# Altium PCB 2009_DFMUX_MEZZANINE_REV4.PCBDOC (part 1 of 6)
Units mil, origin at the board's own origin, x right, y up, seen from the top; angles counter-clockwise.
Board outline 4922.86 x 3627.76 mil, 6 copper layers (Top Layer, Internal Plane 1, Mid-Layer 1, Internal Plane 2, Mid-Layer 2, Bottom Layer); 519 components, 606 nets, 2175 pads, 757 vias.
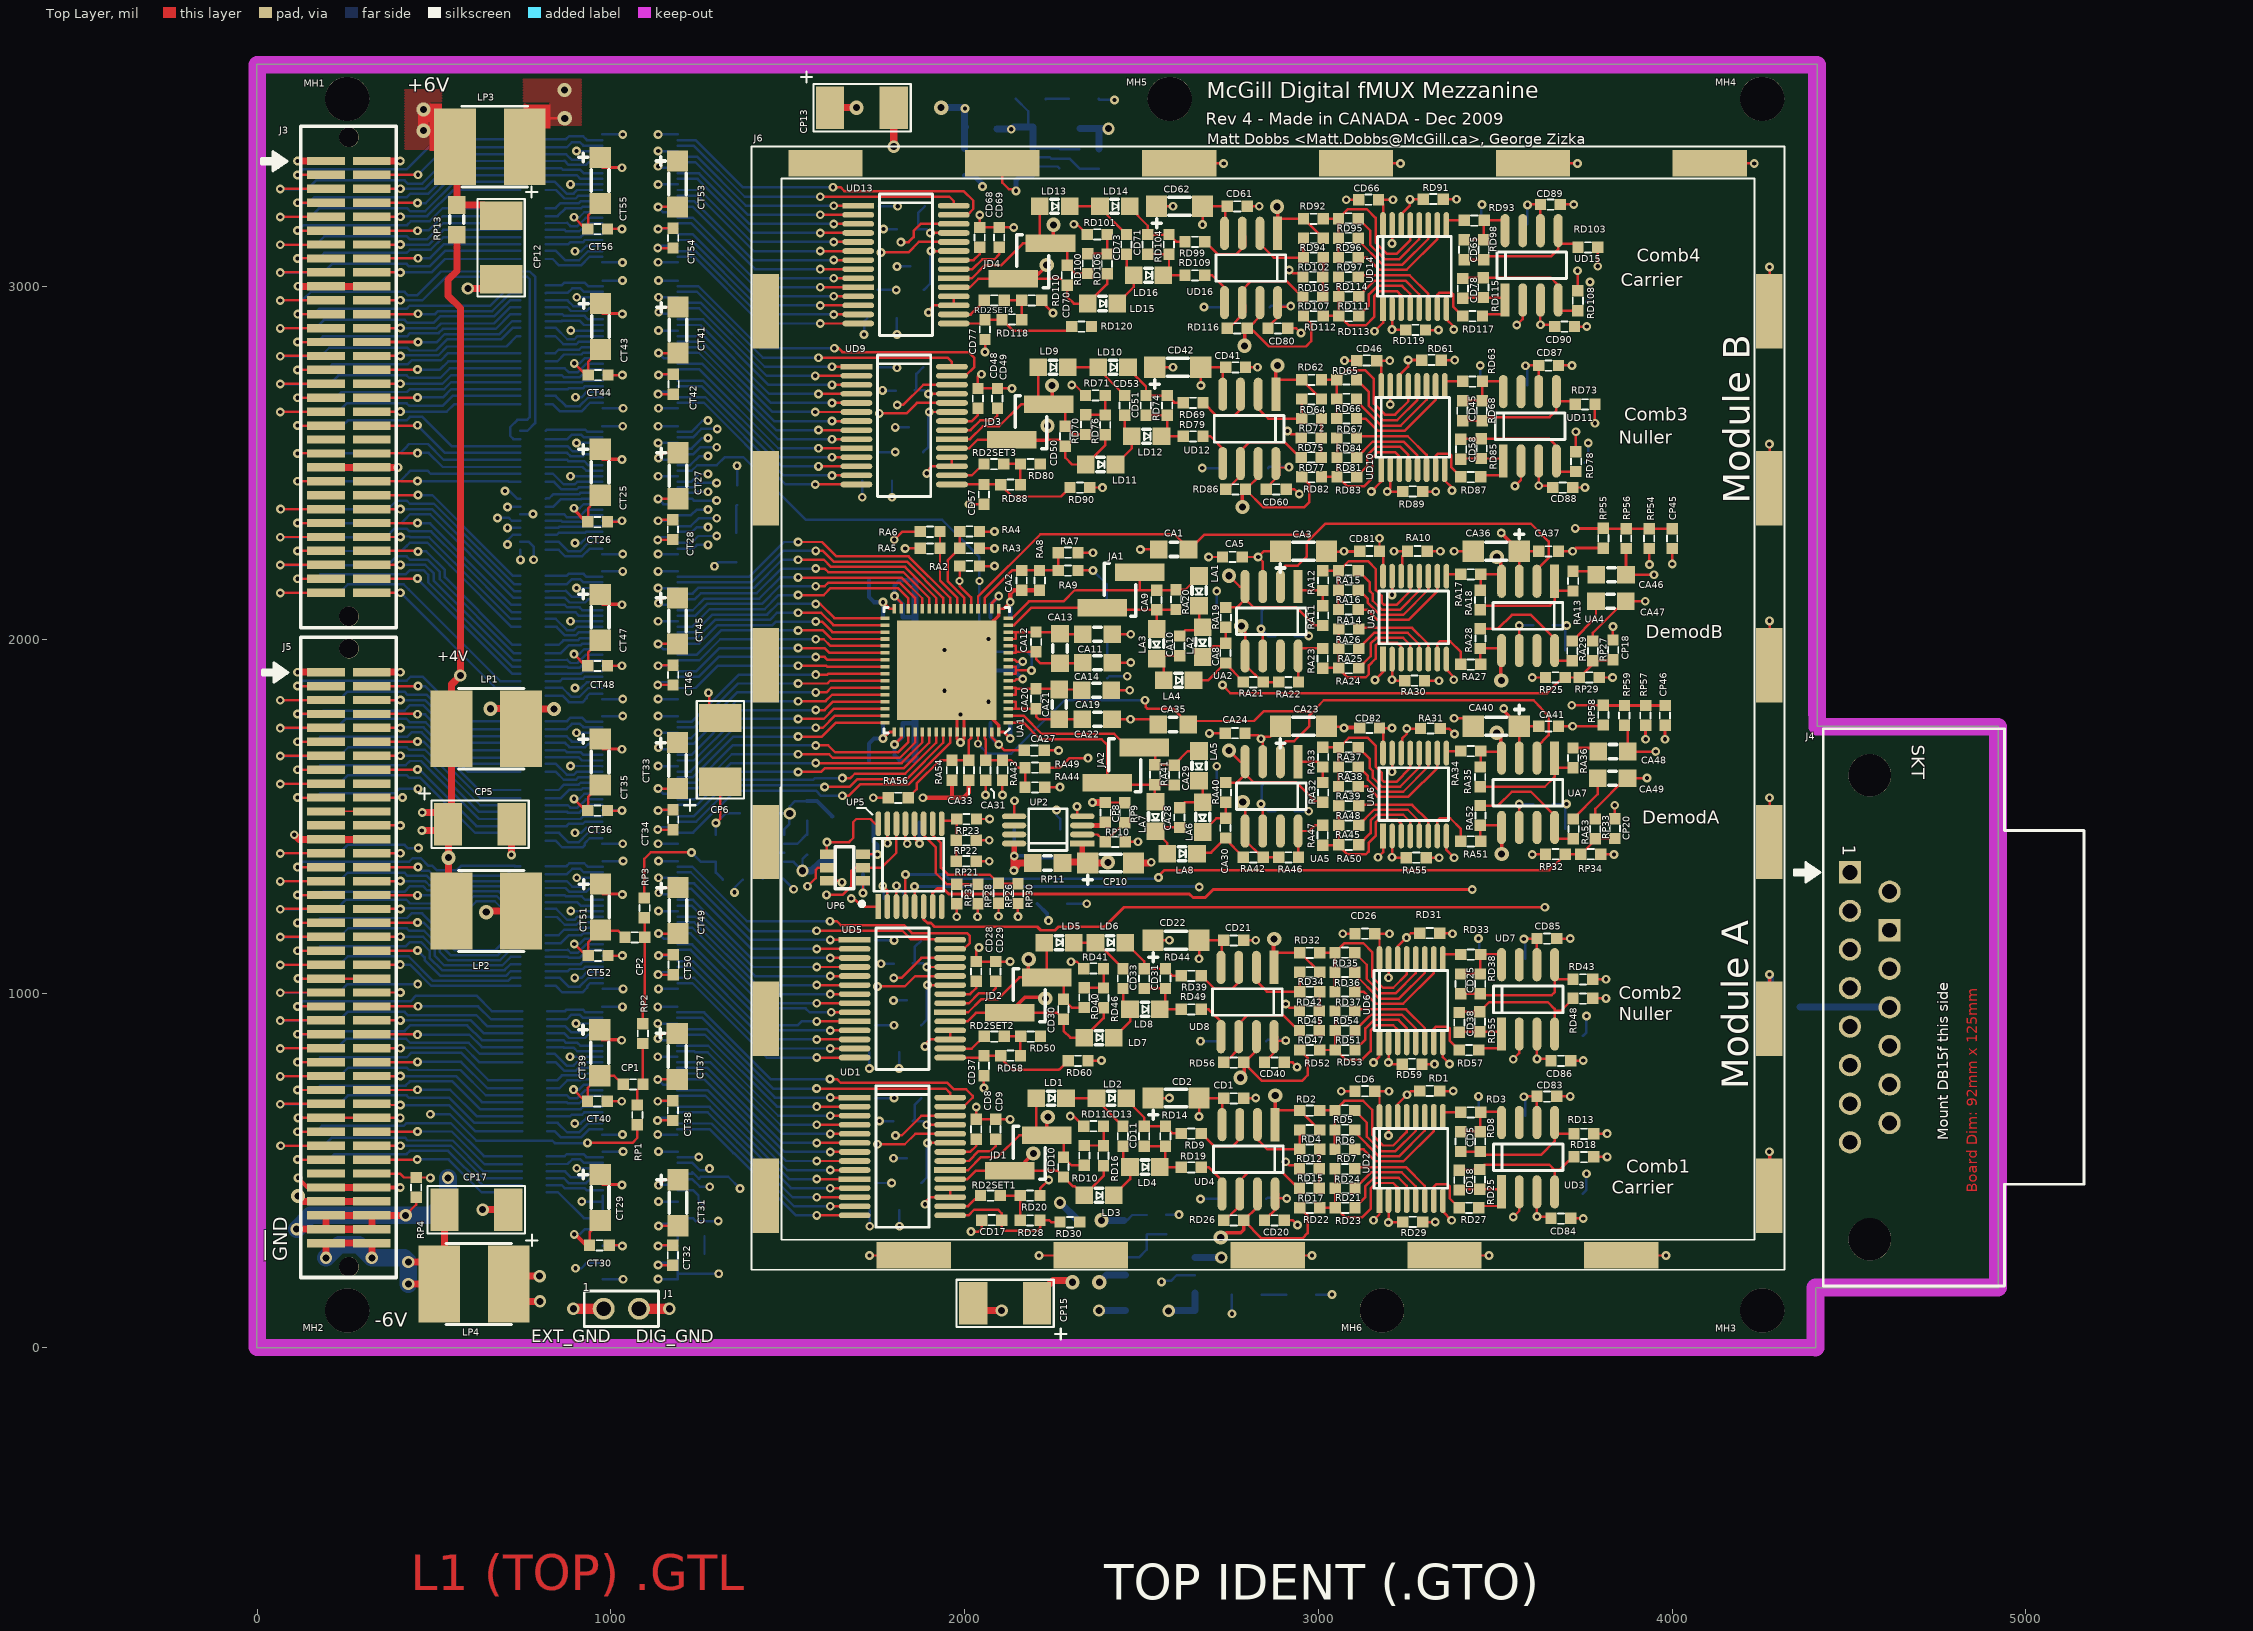
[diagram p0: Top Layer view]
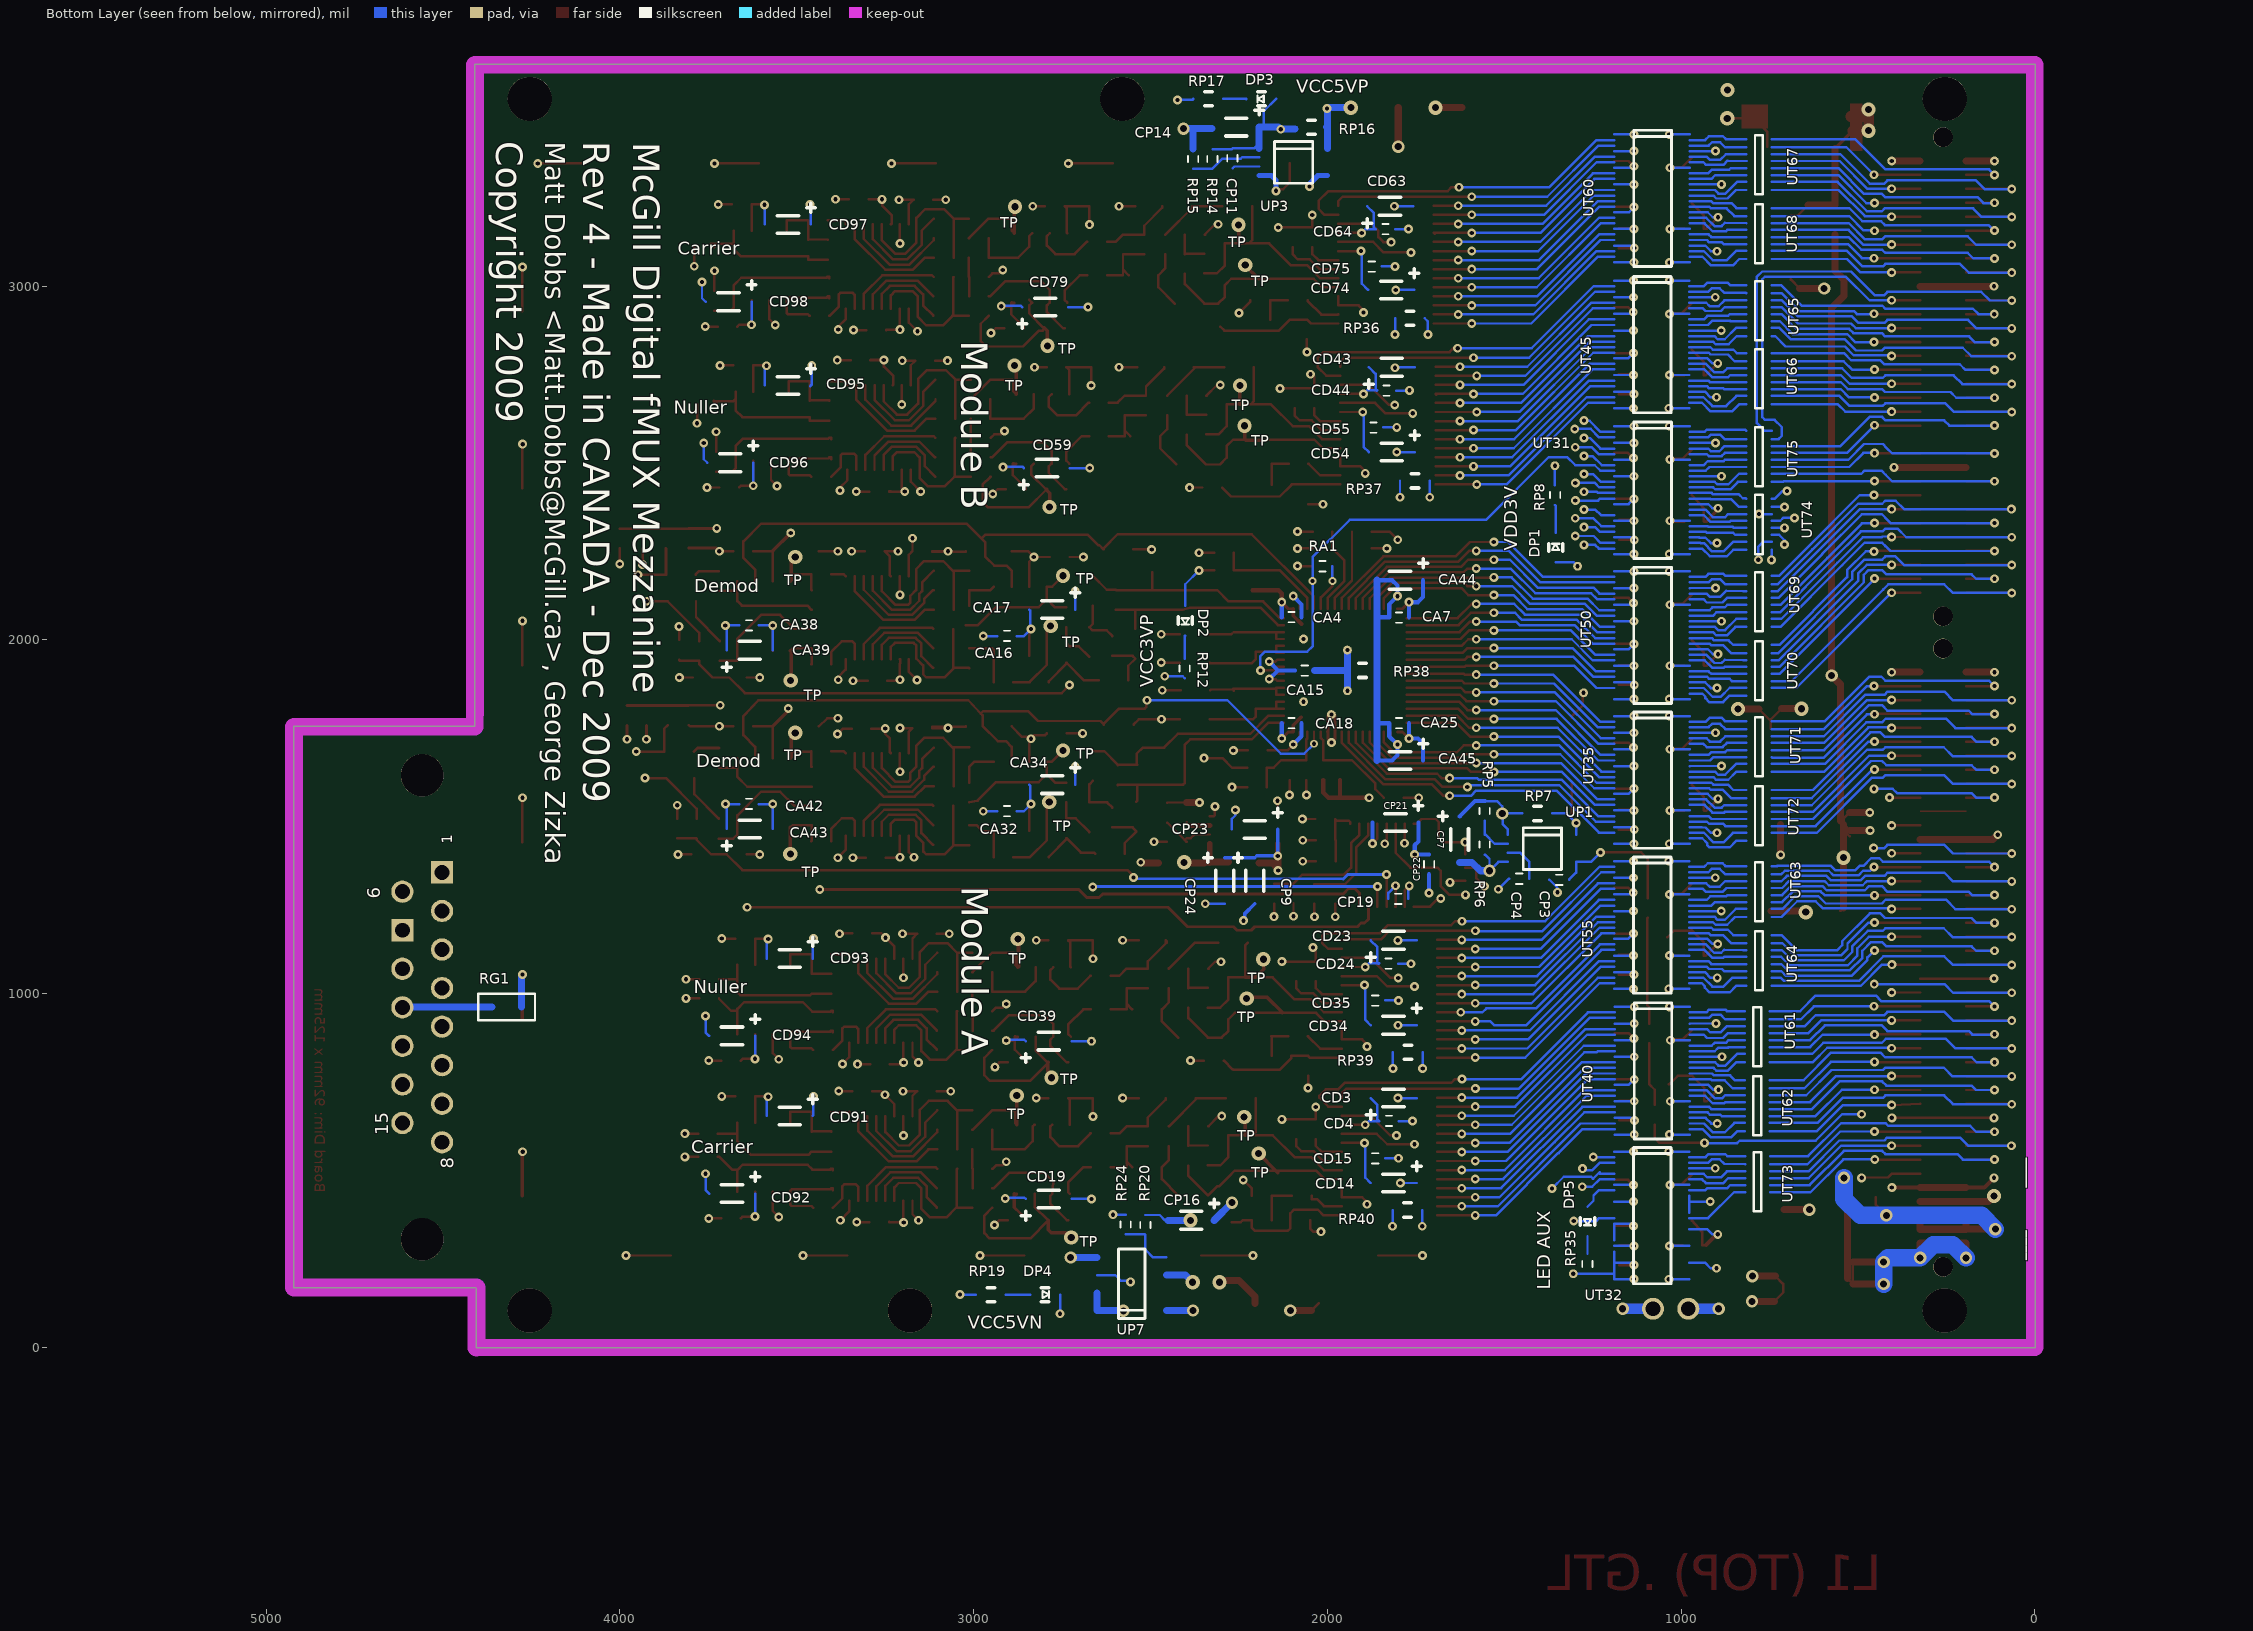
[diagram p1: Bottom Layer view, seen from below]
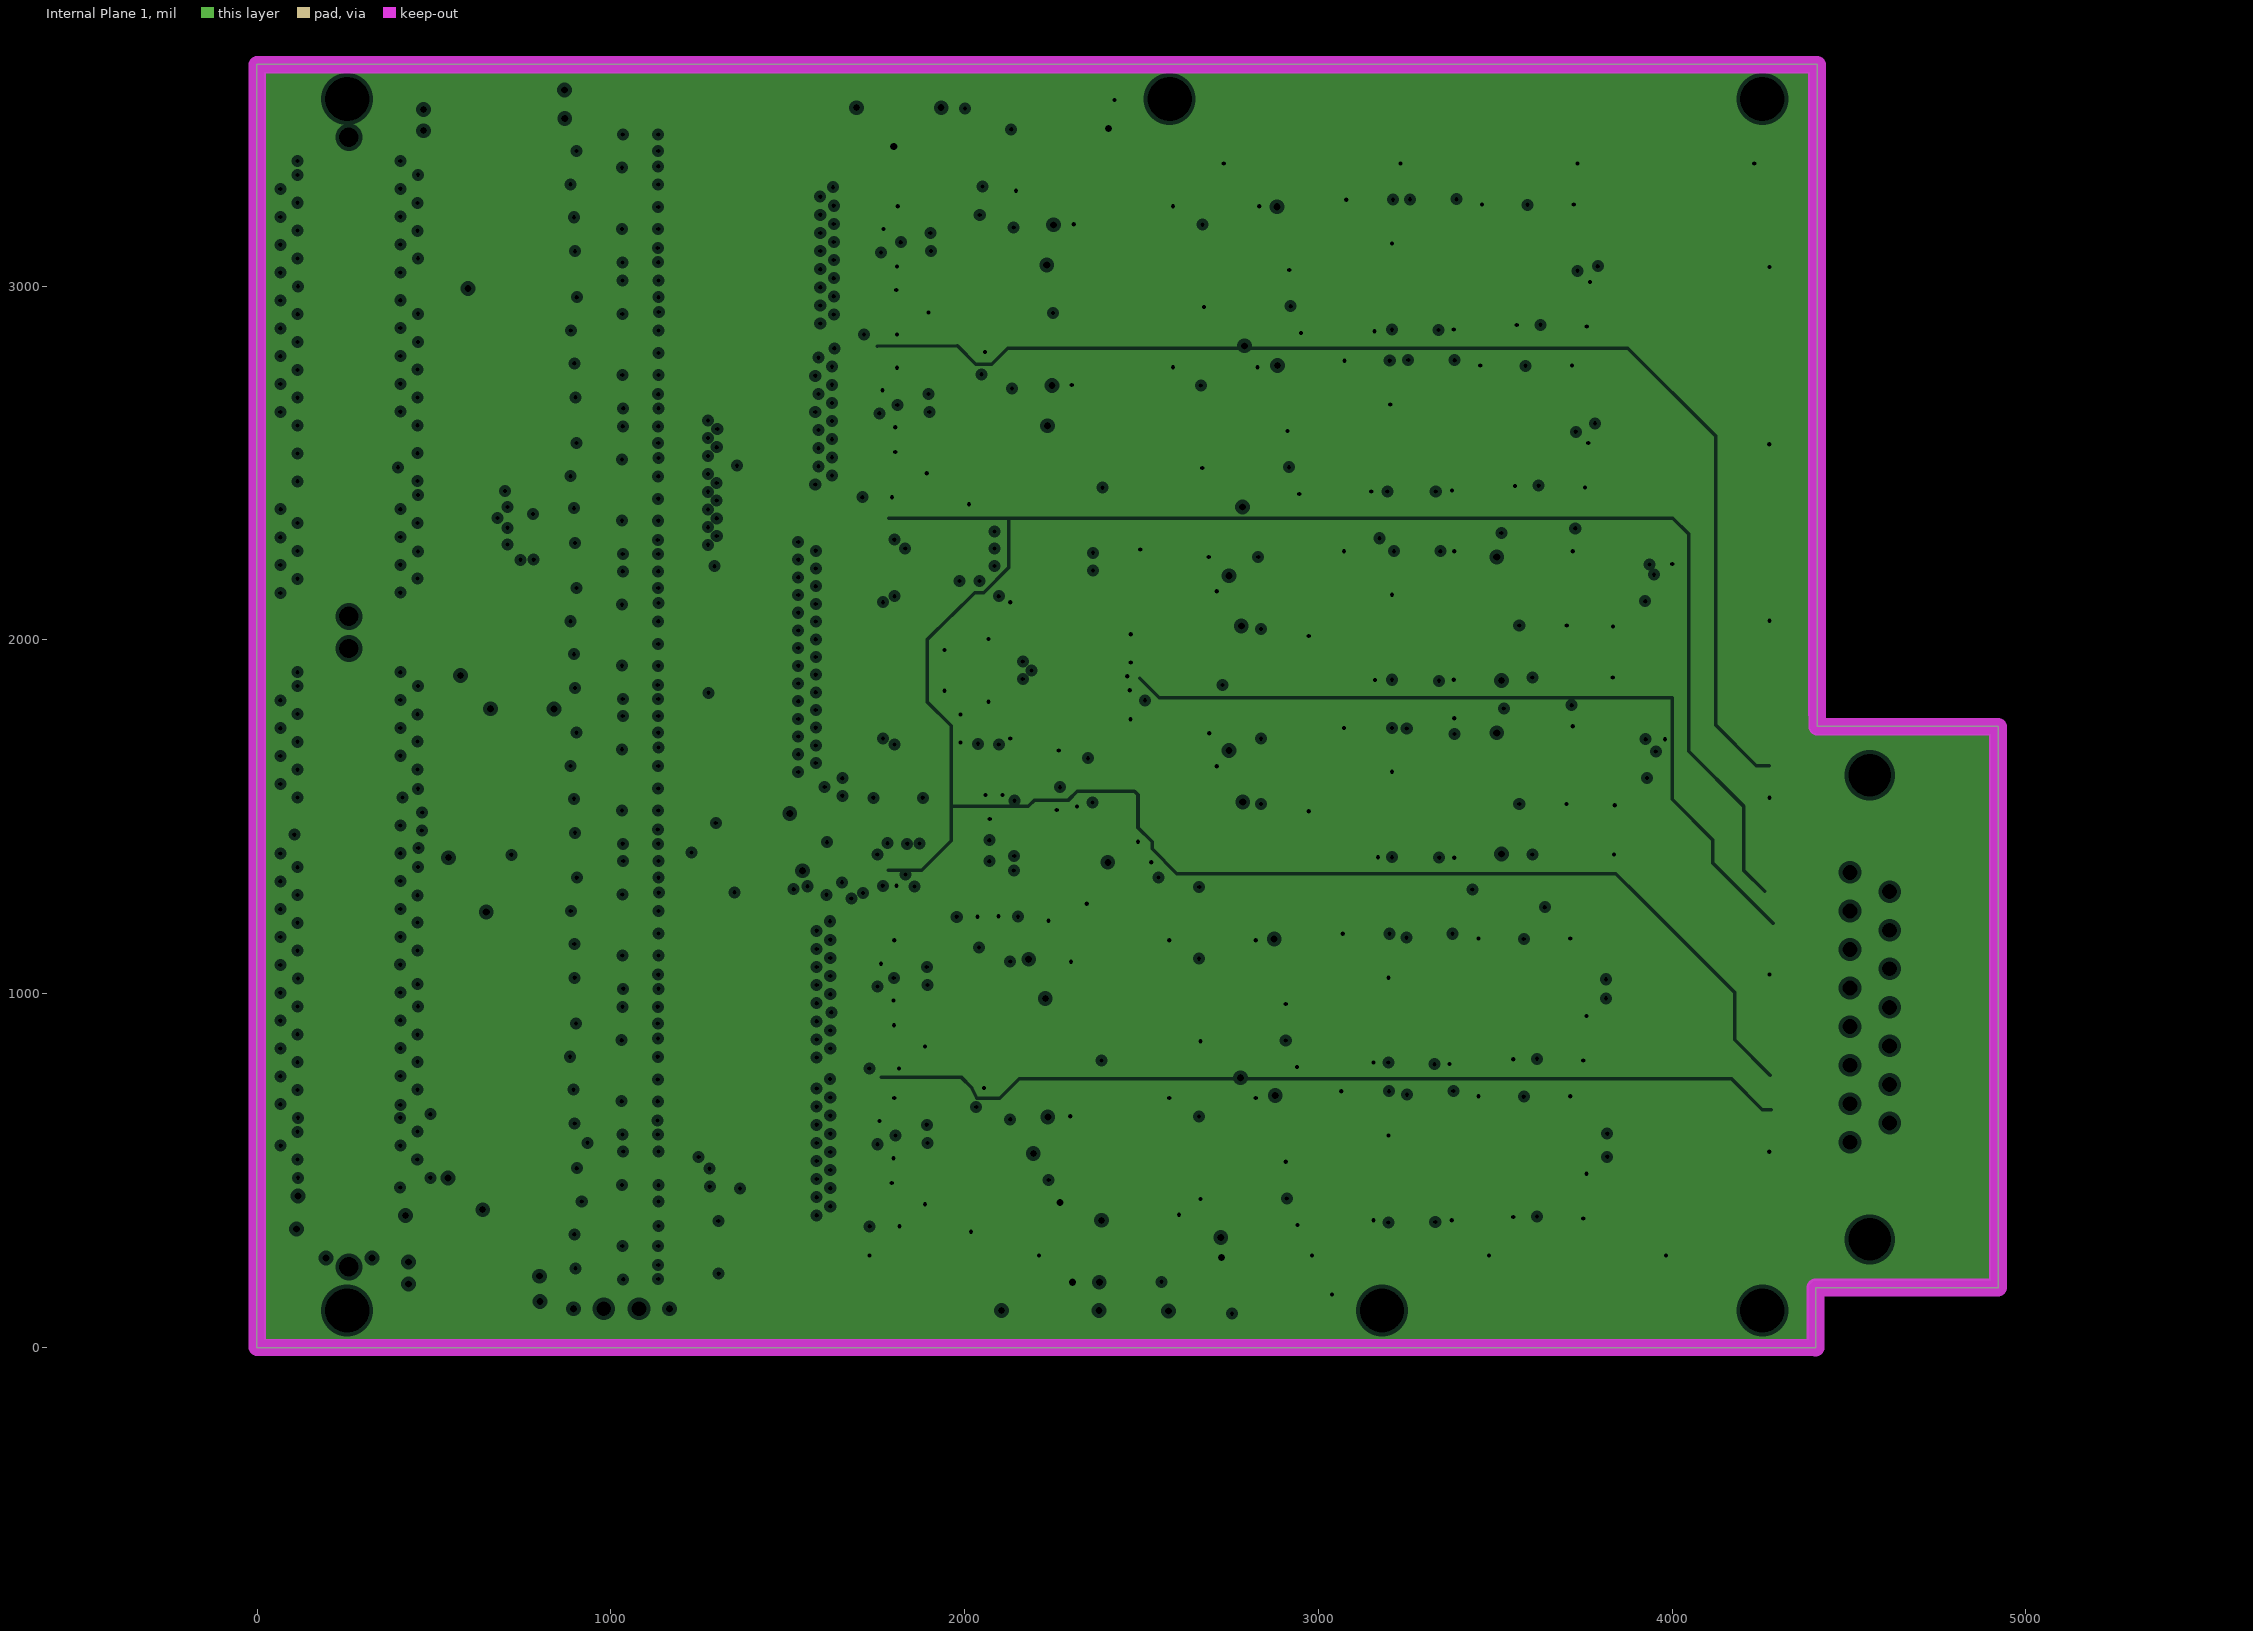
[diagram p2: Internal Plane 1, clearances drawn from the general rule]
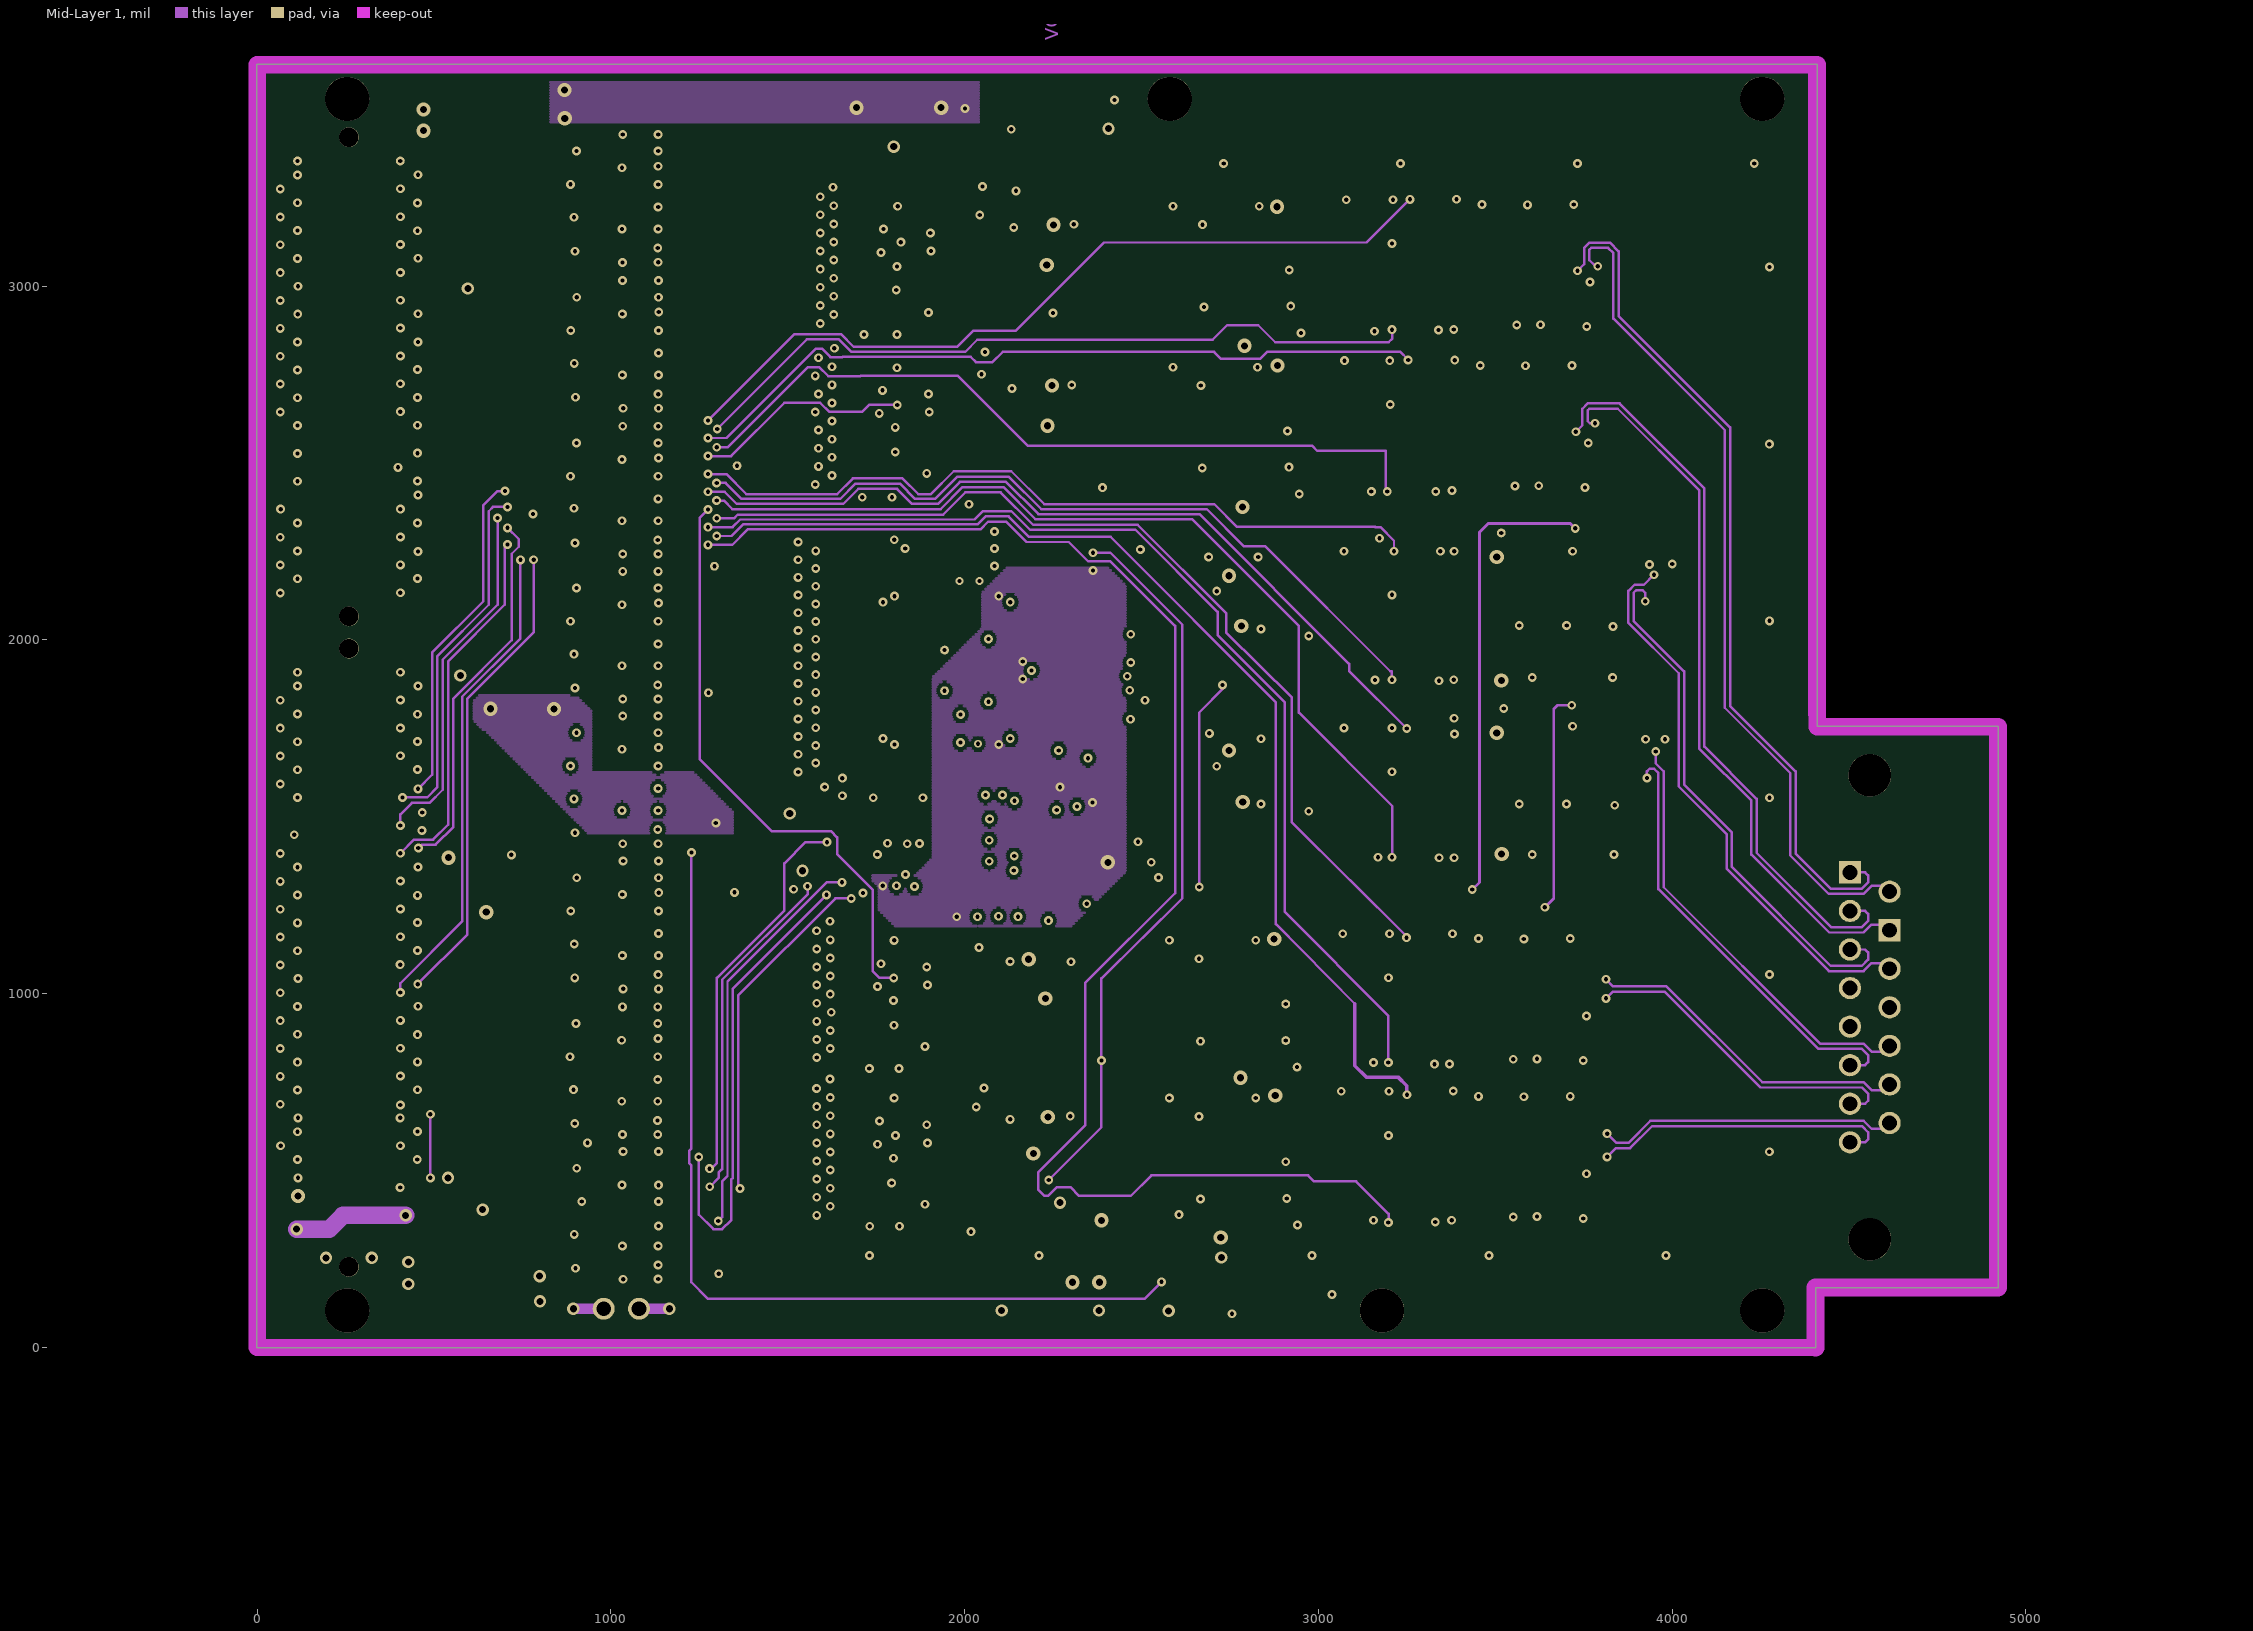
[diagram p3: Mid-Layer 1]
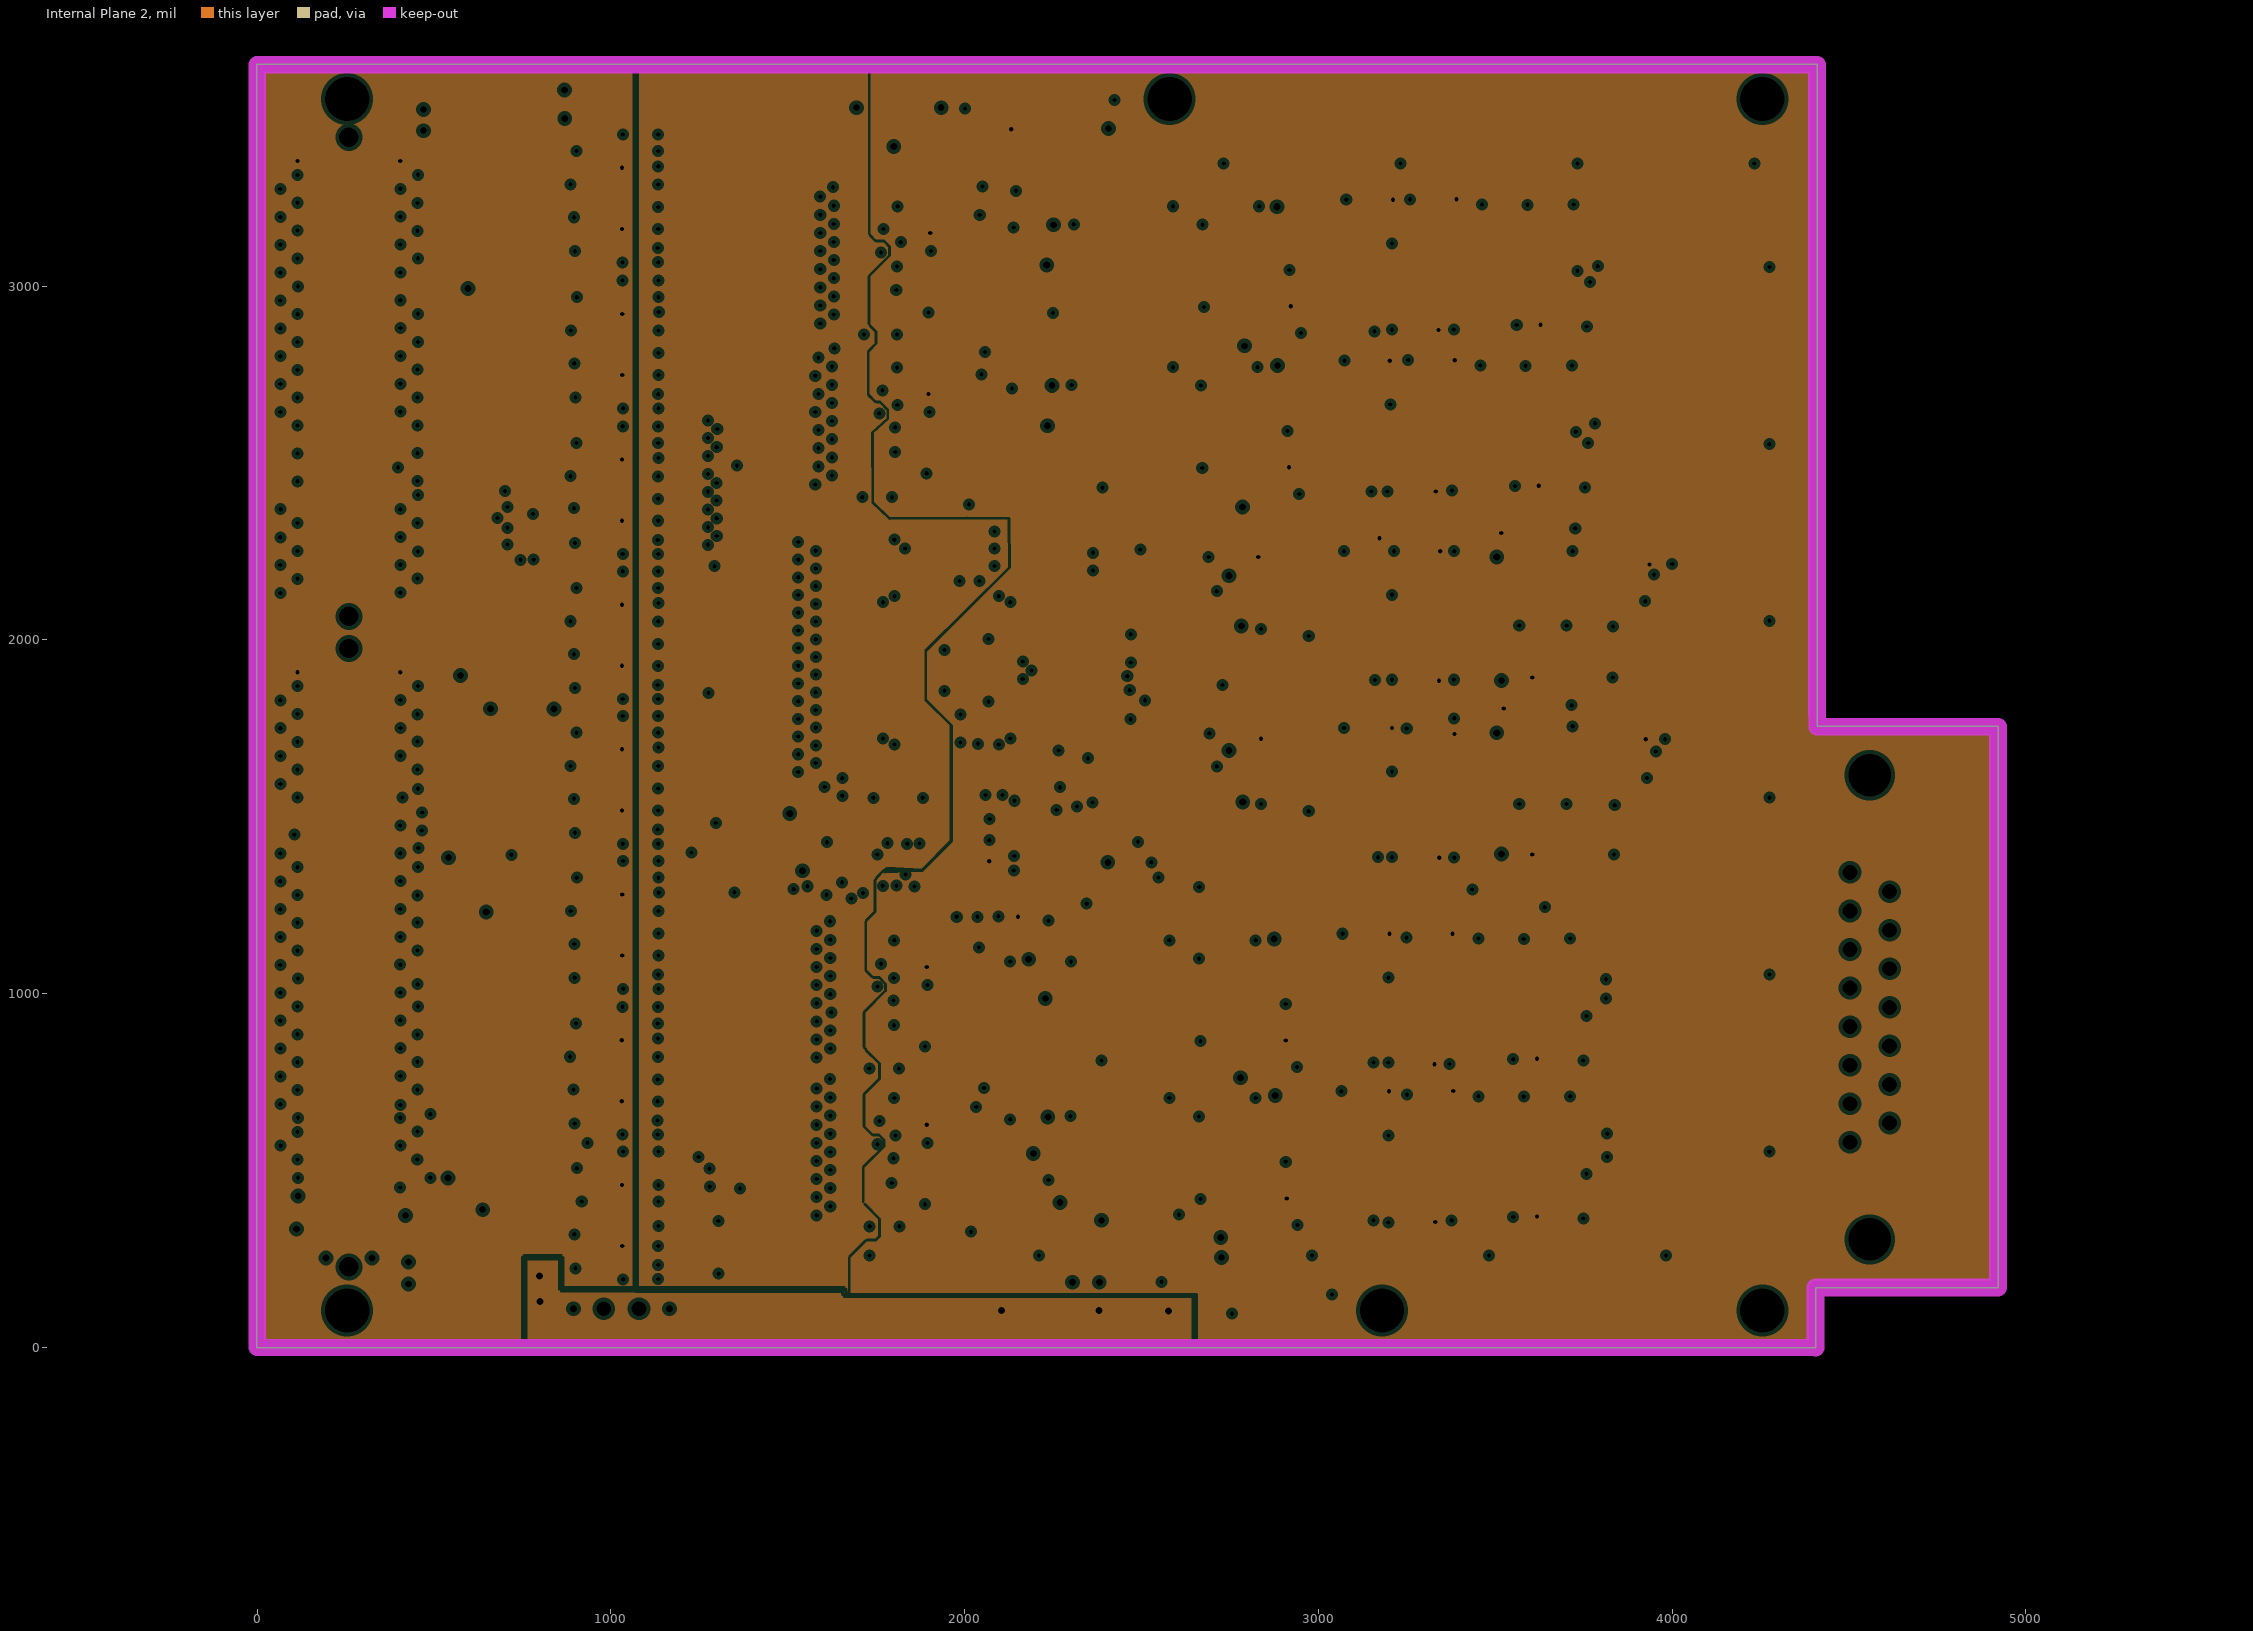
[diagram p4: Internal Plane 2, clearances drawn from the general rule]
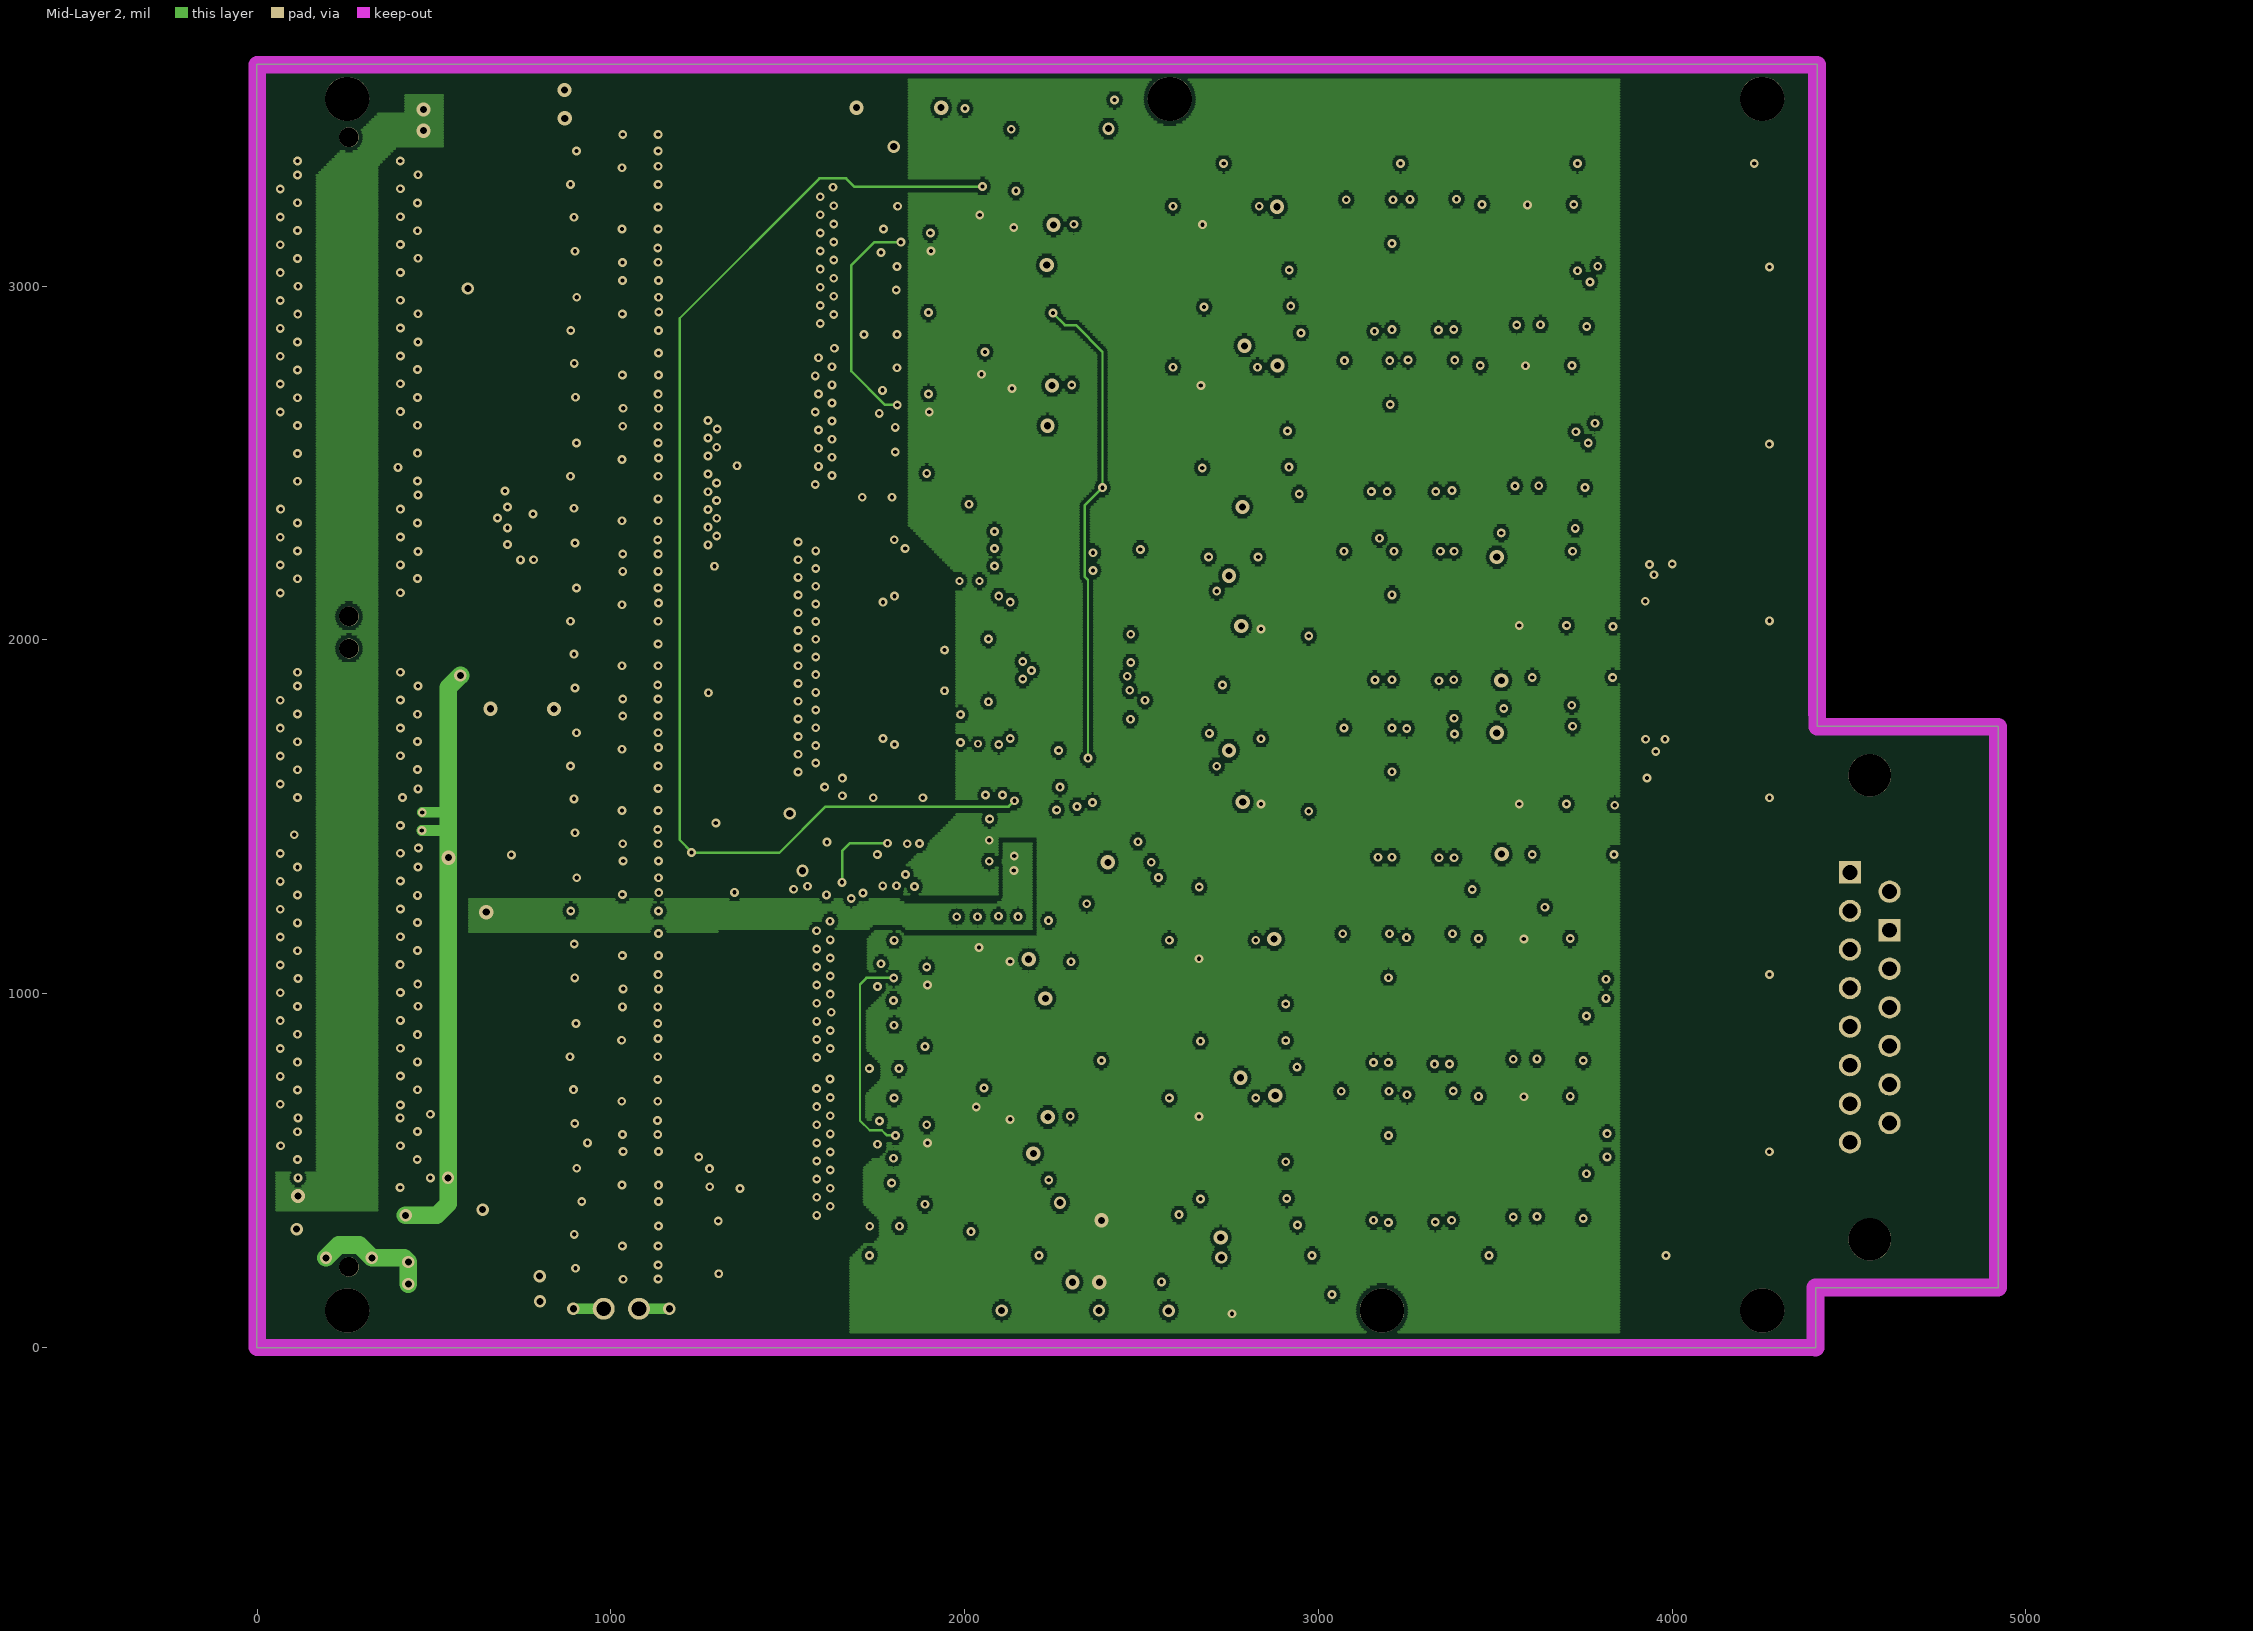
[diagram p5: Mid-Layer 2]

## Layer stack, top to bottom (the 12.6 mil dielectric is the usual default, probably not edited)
Top Layer: signal copper 1.4
Dielectric: core 12.6, FR-4, Dk 4.8
Internal Plane 1: plane copper 1.4, net GND_SIGNAL
Dielectric: prepreg 12.6, FR-4, Dk 4.8
Mid-Layer 1: signal copper 1.4
Dielectric: core 12.6, FR-4, Dk 4.8
Internal Plane 2: plane copper 1.4, net VDD_EXT
Dielectric: prepreg 12.6, FR-4, Dk 4.8
Mid-Layer 2: signal copper 1.4
Dielectric: core 12.6, FR-4, Dk 4.8
Bottom Layer: signal copper 1.4

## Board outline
0,-1.02 cw(c0,0) -1.01,0 -1.01,3625.73 cw(c0,3625.73) 0,3626.75 4409.07,3626.75 cw(c4409.07,3625.73) 4410.08,3625.73 4410.08,1755.02 4920.83,1755.02 cw(c4920.83,1754) 4921.85,1754 4921.85,169 cw(c4920.83,169) 4920.83,167.98 4406.02,167.98 4406.02,0 cw(c4405,0) 4405,-1.02

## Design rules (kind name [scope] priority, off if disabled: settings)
Clearance Clearance_1 [(InPoly)] p1: gap=10
Clearance [All] p2: gap=6
ComponentClearance [All] p1 off: gap=10 collisioncheckmode=3 verticalgap=10 showdistances=FALSE
FabricationTestPointUsage TestPointUsage [All] p1: valid=0 allowmultiple=FALSE
FabricationTestpoint Testpoint [All] p1: side=3 testpointundercomponent=TRUE minsize=40 maxsize=100 preferedsize=60 minholesize=20 maxholesize=40 preferedholesize=32 testpointgrid=1 allowsidetop=TRUE allowsidebottom=TRUE usegrid=TRUE gridtolerance=0.01
HoleSize [All] p1: absolutevalues=TRUE maxlimit=250 minlimit=10 maxpercent=80.000 minpercent=20.000
PlaneClearance [All] p1: clearance=11
PlaneConnect PlaneConnect_1 [All] p1: planeconnectstyle=Direct reliefexpansion=20 reliefentries=4 reliefconductorwidth=10 reliefairgap=10
PlaneConnect [All] p2: planeconnectstyle=Relief reliefexpansion=20 reliefentries=4 reliefconductorwidth=10 reliefairgap=12
PolygonConnect [All] p1: connectstyle=Relief reliefconductorwidth=10 reliefentries=4 polygonreliefangle="90 Angle"
RoutingLayers [All] p1: top layer_v5=TRUE mid layer 1_v5=FALSE mid layer 2_v5=FALSE bottom layer_v5=TRUE
RoutingVias [All] p1: holewidth=12 width=25 viastyle="Through Hole" minholewidth=12 minwidth=22 maxholewidth=28 maxwidth=50
SilkscreenOverComponentPads [All] p1: minsilkscreentomaskgap=10
SolderMaskExpansion [All] p1: expansion=4
Width [All] p1: maxlimit=100 minlimit=2 preferedwidth=7
20 further rules are at their usual default settings.

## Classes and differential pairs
component class "Component Group 1": CA1 CA2 CA3 CA4 CA5 CA7 CA8 CA9 CA10 CA11 CA12 CA13 CA14 CA15 CA16 CA17 CA18 CA19 CA20 CA21 CA22 CA23 CA24 CA25 CA27 CA28 CA29 CA30 CA31 CA32 CA33 CA34 CA35 CA36 CA37 CA38 CA39 CA40 CA41 CA42 CA43 CA44 CA45 CA46 CA47 CA48 CA49 CD81 CD82 JA1 JA2 LA1 LA2 LA3 LA4 LA5 LA6 LA7 LA8 RA1 RA2 RA3 RA4 RA5 RA6 RA7 RA8 RA9 RA10 RA11 RA12 RA13 RA14 RA15 RA16 RA17 RA18 RA19 RA20 RA21 RA22 RA23 RA24 RA25 RA26 RA27 RA28 RA29 RA30 RA31 RA32 RA33 RA34 RA35 RA36 RA37 RA38 RA39 RA40 RA41 RA42 RA43 RA44 RA45 RA46 RA47 RA48 RA49 RA50 RA51 RA52 RA53 RA54 RA55 RA56 UA1 UA2 UA3 UA4 UA5 UA6 UA7

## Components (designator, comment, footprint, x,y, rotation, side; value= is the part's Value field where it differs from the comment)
CA1 "2.2u, 0805, X5R" 0805C 2632.63,2255.43 r180 top
CA2 "100n, 0603" 0603C#1 2161.77,2195.87 r270 top
CA3 "10u A3216 10V LO ESR" TANTA#1 2892.63,2250.43 r0 top
CA4 "100n, 0603" 0603C#2 2073,2063.37 r0 bottom
CA5 "100n, 0603" 0603C#1 2784.63,2234 r180 top
CA7 "100n, 0603" 0603C#2 1825.27,2063.37 r180 bottom
CA8 "120p, 5%, 0603 NP0" 0603C#1 2737.63,1990.43 r270 top
CA9 "120p, 5%, 0603 NP0" 0603C#1 2542.63,2140.43 r270 top
CA10 "200p, 5%, 0603 NP0" 0603C#1 2607.63,2010.43 r270 top
CA11 "1u, 0805, X5R" 0805C 2417.63,2015.43 r180 top
CA12 "100n, 0603" 0603C#1 2201.77,1965.87 r90 top
CA13 "2.2u, 0805, X5R" 0805C 2269.63,1933.43 r90 top
CA14 "1u, 0805, X5R" 0805C 2417.63,1935.43 r180 top
CA15 "100n, 0603" 0603C#2 2091.77,1913.37 r180 bottom
CA16 "100n, 0603" 0603C#2 2877.63,2010.43 r0 bottom
CA17 "10u A3216 10V LO ESR" TANTA#2 2712.63,2085.43 r0 bottom
CA18 "100n, 0603" 0603C#2 2073,1763.91 r0 bottom
CA19 "1u, 0805, X5R" 0805C 2414.63,1857.43 r180 top
CA20 "100n, 0603" 0603C#1 2201.73,1805.37 r90 top
CA21 "2.2u, 0805, X5R" 0805C 2267.63,1775.43 r90 top
CA22 "1u, 0805, X5R" 0805C 2416.63,1775.43 r180 top
CA23 "10u A3216 10V LO ESR" TANTA#1 2892.63,1755.43 r0 top
CA24 "100n, 0603" 0603C#1 2792.63,1735.43 r180 top
CA25 "100n, 0603" 0603C#2 1769.27,1763.91 r0 bottom
CA27 "100n, 0603" 0603C#1 2168.63,1687.37 r0 top
CA28 "200p, 5%, 0603 NP0" 0603C_REV1 2607.63,1525.43 r270 top
CA29 "120p, 5%, 0603 NP0" 0603C#1 2592.63,1645.43 r270 top
CA30 "120p, 5%, 0603 NP0" 0603C#1 2737.63,1495.43 r270 top
CA31 "100n, 0603" 0603C#1 2059.27,1659.37 r270 top
CA32 "100n, 0603" 0603C#2 2877.63,1515.43 r0 bottom
CA33 "100n, 0603" 0603C#1 2011.77,1603.37 r90 top
CA34 "10u A3216 10V LO ESR" TANTA#2 2712.63,1590.43 r0 bottom
CA35 "2.2u, 0805, X5R" 0805C 2547.63,1760.43 r0 top
CA36 "10u A3216 10V LO ESR" TANTA#1 3567.63,2250.43 r180 top
CA37 "100n, 0603" 0603C#1 3622.63,2250.43 r0 top
CA38 "100n, 0603" 0603C#2 3606.63,2040.43 r0 bottom
CA39 "10u A3216 10V LO ESR" TANTA#2 3697.63,1970.43 r180 bottom
CA40 "10u A3216 10V LO ESR" TANTA#1 3567.63,1755.43 r180 top
CA41 "100n, 0603" 0603C#1 3622.63,1755.43 r0 top
CA42 "100n, 0603" 0603C#2 3606.63,1535.43 r0 bottom
CA43 "10u A3216 10V LO ESR" TANTA#2 3697.63,1465.43 r180 bottom
CA44 "10u A3216 10V LO ESR" TANTA#2 1729.27,2168.37 r0 bottom
CA45 "10u A3216 10V LO ESR" TANTA#2 1729.27,1658.91 r0 bottom
CA46 "100n, 0805" 0805C 3869.63,2184 r180 top
CA47 "100n, 0805" 0805C 3784.63,2109 r0 top
CA48 "100n, 0805" 0805C 3874.63,1684 r180 top
CA49 "100n, 0805" 0805C 3789.63,1609 r0 top
CD1 "100n, 0603" 0603C#1 2732.63,704.43 r0 top
CD2 "10u A3216 10V LO ESR" TANTA#1 2532.63,704.43 r0 top
CD3 "10u A3216 10V LO ESR" TANTA#2 1877.63,704.43 r180 bottom
CD4 "100n, 0603" 0603C#2 1797.63,639.37 r0 bottom
CD5 "DNL, 0603" 0603C#1 3402.63,609.43 r270 top
CD6 "100n, 0603" 0603C#1 3159.63,724 r180 top
CD8 "100n, 0603" 0603C#1 2032.63,644.43 r270 top
CD9 "100n, 0603" 0603C#1 2087.63,644.43 r270 top
CD10 "120p, 5%, 0603 NP0" 0603C#1 2279.63,537.43 r270 top
CD11 "120p, 5%, 0603 NP0" 0603C#1 2507.63,624.43 r270 top
CD13 "200p, 5%, 0603 NP0" 0603C#1 2447.63,624.43 r270 top
CD14 "10u A3216 10V LO ESR" TANTA#2 1747.63,464.43 r0 bottom
CD15 "100n, 0603" 0603C#2 1892.63,534.43 r180 bottom
CD17 "100n, 0603" 0603C#1 2104.63,359 r180 top
CD18 "DNL, 0603" 0603C#1 3397.63,444.43 r90 top
CD19 "10u A3216 10V LO ESR" TANTA#2 2852.63,419.43 r180 bottom
CD20 "100n, 0603" 0603C#1 2847.63,359.43 r0 top
CD21 "100n, 0603" 0603C#1 2732.63,1150.43 r0 top
CD22 "10u A3216 10V LO ESR" TANTA#1 2532.63,1150.43 r0 top
CD23 "10u A3216 10V LO ESR" TANTA#2 1877.63,1150.43 r180 bottom
CD24 "100n, 0603" 0603C#2 1799.63,1084 r0 bottom
CD25 "DNL, 0603" 0603C#1 3402.63,1055.43 r270 top
CD26 "100n, 0603" 0603C#1 3159.63,1169 r180 top
CD28 "100n, 0603" 0603C#1 2032.63,1090.43 r270 top
CD29 "100n, 0603" 0603C#1 2087.63,1090.43 r270 top
CD30 "120p, 5%, 0603 NP0" 0603C#1 2279.63,983.43 r270 top
CD31 "120p, 5%, 0603 NP0" 0603C#1 2507.63,1070.43 r270 top
CD33 "200p, 5%, 0603 NP0" 0603C#1 2447.63,1070.43 r270 top
CD34 "10u A3216 10V LO ESR" TANTA#2 1747.63,910.43 r0 bottom
CD35 "100n, 0603" 0603C#2 1892.63,980.43 r180 bottom
CD37 "100n, 0603" 0603C#1 2054.63,824 r270 top
CD38 "DNL, 0603" 0603C#1 3397.63,890.43 r90 top
CD39 "10u A3216 10V LO ESR" TANTA#2 2852.63,865.43 r180 bottom
CD40 "100n, 0603" 0603C#1 2847.63,805.43 r0 top
CD41 "100n, 0603" 0603C#1 2737.63,2770.43 r0 top
CD42 "10u A3216 10V LO ESR" TANTA#1 2537.63,2770.43 r0 top
CD43 "10u A3216 10V LO ESR" TANTA#2 1882.63,2770.43 r180 bottom
CD44 "100n, 0603" 0603C#2 1804.63,2704 r0 bottom
CD45 "DNL, 0603" 0603C#1 3407.63,2675.43 r270 top
CD46 "100n, 0603" 0603C#1 3164.63,2789 r180 top
CD48 "100n, 0603" 0603C#1 2037.63,2710.43 r270 top
CD49 "100n, 0603" 0603C#1 2092.63,2710.43 r270 top
CD50 "120p, 5%, 0603 NP0" 0603C#1 2284.63,2603.43 r270 top
CD51 "120p, 5%, 0603 NP0" 0603C#1 2512.63,2690.43 r270 top
CD53 "200p, 5%, 0603 NP0" 0603C#1 2452.63,2690.43 r270 top
CD54 "10u A3216 10V LO ESR" TANTA#2 1752.63,2530.43 r0 bottom
CD55 "100n, 0603" 0603C#2 1897.63,2600.43 r180 bottom
CD57 "100n, 0603" 0603C#1 2054.63,2439 r270 top
CD58 "DNL, 0603" 0603C#1 3402.63,2510.43 r90 top
CD59 "10u A3216 10V LO ESR" TANTA#2 2857.63,2485.43 r180 bottom
CD60 "100n, 0603" 0603C#1 2852.63,2425.43 r0 top
CD61 "100n, 0603" 0603C#1 2742.63,3225.43 r0 top
CD62 "10u A3216 10V LO ESR" TANTA#1 2542.63,3225.43 r0 top
CD63 "10u A3216 10V LO ESR" TANTA#2 1887.63,3225.43 r180 bottom
CD64 "100n, 0603" 0603C#2 1807.63,3160.37 r0 bottom
CD65 "DNL, 0603" 0603C#1 3412.63,3130.43 r270 top
CD66 "100n, 0603" 0603C#1 3169.63,3244 r180 top
CD68 "100n, 0603" 0603C#1 2042.63,3165.43 r270 top
CD69 "100n, 0603" 0603C#1 2097.63,3165.43 r270 top
CD70 "120p, 5%, 0603 NP0" 0603C#1 2289.63,3058.43 r270 top
CD71 "120p, 5%, 0603 NP0" 0603C#1 2517.63,3145.43 r270 top
CD73 "200p, 5%, 0603 NP0" 0603C#1 2457.63,3145.43 r270 top
CD74 "10u A3216 10V LO ESR" TANTA#2 1754.63,2989 r0 bottom
CD75 "100n, 0603" 0603C#2 1902.63,3055.43 r180 bottom
CD77 "100n, 0603" 0603C#1 2057.63,2905 r270 top
CD78 "DNL, 0603" 0603C#1 3407.63,2965.43 r90 top
CD79 "10u A3216 10V LO ESR" TANTA#2 2862.63,2940.43 r180 bottom
CD80 "100n, 0603" 0603C#1 2857.63,2880.43 r0 top
CD81 "100n, 0603" 0603C#1 3172.63,2250.43 r180 top
CD82 "100n, 0603" 0603C#1 3172.63,1750.43 r180 top
CD83 "100n, 0603" 0603C#1 3617.63,709.43 r0 top
CD84 "100n, 0603" 0603C#1 3657.63,364.43 r0 top
CD85 "100n, 0603" 0603C#1 3617.63,1155.43 r0 top
CD86 "100n, 0603" 0603C#1 3657.63,810.43 r0 top
CD87 "100n, 0603" 0603C#1 3622.63,2775.43 r0 top
CD88 "100n, 0603" 0603C#1 3662.63,2430.43 r0 top
CD89 "100n, 0603" 0603C#1 3627.63,3230.43 r0 top
CD90 "100n, 0603" 0603C#1 3667.63,2885.43 r0 top
CD91 "10u A3216 10V LO ESR" TANTA#2 3454.63,654 r0 bottom
CD92 "10u A3216 10V LO ESR" TANTA#2 3617.63,434.43 r0 bottom
CD93 "10u A3216 10V LO ESR" TANTA#2 3454.63,1099 r0 bottom
CD94 "10u A3216 10V LO ESR" TANTA#2 3617.63,880.43 r0 bottom
CD95 "10u A3216 10V LO ESR" TANTA#2 3459.63,2719 r0 bottom
CD96 "10u A3216 10V LO ESR" TANTA#2 3622.63,2500.43 r0 bottom
CD97 "10u A3216 10V LO ESR" TANTA#2 3459.63,3174 r0 bottom
CD98 "10u A3216 10V LO ESR" TANTA#2 3627.63,2955.43 r0 bottom
CP1 "100n 0603" 0603C#1 1034.63,744 r0 top
CP2 "100n 0603" 0603C#1 1039.63,1159 r0 top
CP3 "100n 0603" 0603C#2 1372.63,1322 r180 bottom
CP4 "10n 0603" 0603C#2 1429.63,1324 r0 bottom
CP5 "33u, 16V, 20%, 4532C, X5R" TANT4532 539.63,1478.37 r0 top
CP6 "33u, 16V, 20%, 4532C, X5R" TANT4532 1309.63,1599 r90 top
CP7 "10u A3216 10V LO ESR" TANTA#2 1625.93,1500.8 r270 bottom
CP8 "10n 0603" 0603C#1 2397.63,1484 r90 top
CP9 "33u, 16V, 20%, 4532C, X5R" TANTA#2 2205,1384 r270 bottom
CP10 "10u A3216 10V LO ESR" TANTA#1 2347.63,1369 r0 top
CP11 "10n 0603" 0603C#2 2267.63,3389 r270 bottom
CP12 "33u, 16V, 20%, 4532C, X5R" TANT4532 689.63,3199 r270 top
CP13 "33u, 16V, 20%, 4532C, X5R" TANT4532 1619.63,3504 r0 top
CP14 "10u A3216 10V LO ESR" TANTA#2 2192.63,3449 r0 bottom
CP15 "33u, 16V, 20%, 4532C, X5R" TANT4532 2204.63,124 r180 top
CP16 "10u A3216 10V LO ESR" TANTA#2 2319.63,359 r0 bottom
CP17 "33u, 16V, 20%, 4532C, X5R" TANT4532 709.63,389 r180 top
CP18 "100n, 0603" 0603C#1 3832.63,1943.37 r90 top
CP19 "100n, 0603" 0603C#2 1827.63,1268.37 r180 bottom
CP20 "100n, 0603" 0603C#1 3837.63,1438.37 r90 top
CP21 "10u A3216 10V LO ESR" TANTA#2 1742.63,1483.37 r0 bottom
CP22 "100n, 0603" 0603C#2 1712.63,1337.37 r90 bottom
CP23 "10uF,3216,low ESR" TANTA#2 2140,1464 r0 bottom
CP24 "10uF,3216,low ESR" TANTA#2 2290,1384 r270 bottom
CP45 "100n, 0603" 0603C#1 4000,2314 r270 top
CP46 "100n, 0603" 0603C#1 3980,1814 r270 top
CT25 "10u A3216 10V LO ESR" TANTA#1 969.63,2538.37 r270 top
CT26 "100n, 0603" 0603C#1 934.63,2333.37 r0 top
CT27 "10u A3216 10V LO ESR" TANTA#1 1189.63,2528.37 r270 top
CT28 "100n, 0603" 0603C#1 1174.63,2283.37 r90 top
CT29 "10u A3216 10V LO ESR" TANTA#1 969.63,488.37 r270 top
CT30 "100n, 0603" 0603C#1 939.63,288.37 r0 top
CT31 "10u A3216 10V LO ESR" TANTA#1 1189.63,473.37 r270 top
CT32 "100n, 0603" 0603C#1 1174.63,232.37 r90 top
CT33 "10u A3216 10V LO ESR" TANTA#1 1188.63,1709.37 r270 top
CT34 "100n, 0603" 0603C#1 1175.63,1463.37 r90 top
CT35 "10u A3216 10V LO ESR" TANTA#1 969.63,1719.37 r270 top
CT36 "100n, 0603" 0603C#1 934.63,1517.37 r0 top
CT37 "10u A3216 10V LO ESR" TANTA#1 1187.63,887.37 r270 top
CT38 "100n, 0603" 0603C#1 1174.63,641.37 r90 top
CT39 "10u A3216 10V LO ESR" TANTA#1 968.63,897.37 r270 top
CT40 "100n, 0603" 0603C#1 933.63,695.37 r0 top
CT41 "10u A3216 10V LO ESR" TANTA#1 1189.63,2940.37 r270 top
CT42 "100n, 0603" 0603C#1 1176.63,2694.37 r90 top
CT43 "10u A3216 10V LO ESR" TANTA#1 970.63,2950.37 r270 top
CT44 "100n, 0603" 0603C#1 935.63,2748.37 r0 top
CT45 "10u A3216 10V LO ESR" TANTA#1 1188.63,2118.37 r270 top
CT46 "100n, 0603" 0603C#1 1175.63,1872.37 r90 top
CT47 "10u A3216 10V LO ESR" TANTA#1 969.63,2128.37 r270 top
CT48 "100n, 0603" 0603C#1 934.63,1926.37 r0 top
CT49 "10u A3216 10V LO ESR" TANTA#1 1189.63,1299.37 r270 top
CT50 "100n, 0603" 0603C#1 1176.63,1053.37 r90 top
CT51 "10u A3216 10V LO ESR" TANTA#1 970.63,1309.37 r270 top
CT52 "100n, 0603" 0603C#1 935.63,1107.37 r0 top
CT53 "10u A3216 10V LO ESR" TANTA#1 1188.63,3353.37 r270 top
CT54 "100n, 0603" 0603C#1 1175.63,3107.37 r90 top
CT55 "10u A3216 10V LO ESR" TANTA#1 969.63,3363.37 r270 top
CT56 "100n, 0603" 0603C#1 934.63,3161.37 r0 top
DP1 "LED, 0805, Green" 0805L#1 1354.63,2219 r90 bottom
DP2 "LED, 0805, Green" 0805L#1 2401.63,2096 r270 bottom
DP3 "LED, 0805, Green" 0805L#1 2144.63,3529 r0 bottom
DP4 "LED, 0805, Green" 0805L#1 2839.63,149 r180 bottom
DP5 "LED, 0805, Yellow" 0805L#1 1264.63,397.37 r270 bottom
J1 "Header SM Amp146128-1" BLKCON.100/VH/TM1SQS/W.100/2 979.63,109 r0 top
J3 "IEEE1386 Amp120527-1 Plug 64pin" CON_AMP_1MM_64PINS 194.63,3353.43 r90 top
J4 "DB15_FEMALE" DSUB/RS.318/TM/15 4502.5,1342.5 r270 top locked
J5 "IEEE1386 Amp120527-2 Plug 84pin" CON_AMP_1MM_84PINS 194.63,1908.37 r90 top
J6 "CONN FLEX 23" "SHIELD 2.75X3.00" 4237.63,3309 r270 top locked
JA1 "Header2, SM, 0.1" HEADER_AMP146128 2494.27,2190.87 r270 top
JA2 "Header2, SM, 0.1" HEADER_AMP146128 2507.63,1695.43 r270 top
JD1 "Header2, SM, 0.1" HEADER_AMP146128 2127.63,499.43 r90 top
JD2 "Header2, SM, 0.1" HEADER_AMP146128 2127.63,945.43 r90 top
JD3 "Header2, SM, 0.1" HEADER_AMP146128 2132.63,2565.43 r90 top
JD4 "Header2, SM, 0.1" HEADER_AMP146128 2137.63,3020.43 r90 top
LA1 "2.7uH, 0805" 0805L#2 2662.63,2180.43 r270 top
LA2 "2.7uH, 0805" 0805L#2 2672.63,2035.43 r270 top
LA3 "2.7uH, 0805" 0805L#2 2542.63,2030.43 r270 top
LA4 "2.7uH, 0805" 0805L#2 2562.63,1885.43 r0 top
LA5 "2.7uH, 0805" 0805L#2 2662.63,1685.43 r270 top
LA6 "2.7uH, 0805" 0805L#2 2672.63,1540.43 r270 top
LA7 "2.7uH, 0805" 0805L#2 2539.63,1542.43 r270 top
LA8 "2.7uH, 0805" 0805L#2 2572.63,1395.43 r0 top
LD1 "2.7uH, 0805" 0805L#2 2202.63,704.43 r0 top
LD2 "2.7uH, 0805" 0805L#2 2372.63,704.43 r0 top
LD3 "2.7uH, 0805" 0805L#2 2337.63,429.43 r0 top
LD4 "2.7uH, 0805" 0805L#2 2467.63,509.43 r0 top
LD5 "2.7uH, 0805" 0805L#2 2224.63,1144 r0 top
LD6 "2.7uH, 0805" 0805L#2 2369.63,1144 r0 top
LD7 "2.7uH, 0805" 0805L#2 2337.63,875.43 r0 top
LD8 "2.7uH, 0805" 0805L#2 2467.63,955.43 r0 top
LD9 "2.7uH, 0805" 0805L#2 2207.63,2770.43 r0 top
LD10 "2.7uH, 0805" 0805L#2 2377.63,2770.43 r0 top
LD11 "2.7uH, 0805" 0805L#2 2342.63,2495.43 r0 top
LD12 "2.7uH, 0805" 0805L#2 2472.63,2575.43 r0 top
LD13 "2.7uH, 0805" 0805L#2 2212.63,3225.43 r0 top
LD14 "2.7uH, 0805" 0805L#2 2382.63,3225.43 r0 top
LD15 "2.7uH, 0805" 0805L#2 2347.63,2950.43 r0 top
LD16 "2.7uH, 0805" 0805L#2 2477.63,3030.43 r0 top
LP1 "68uH, 0.61A, 460mOhm, PM54-680K" CHOKEPM54 549.63,1748.37 r0 top
LP2 "68uH, 0.61A, 460mOhm, PM54-680K" CHOKEPM54 549.63,1233.37 r0 top
LP3 "68uH, 0.61A, 460mOhm, PM54-680K" CHOKEPM54 559.63,3394 r0 top
LP4 "68uH, 0.61A, 460mOhm, PM54-680K" CHOKEPM54 514.63,179 r0 top
MH1 "mounting hole" MTHOLE.125 254.63,3529 r0 top
MH2 "mounting hole" MTHOLE.125 254.63,104 r0 top
MH3 "mounting hole" MTHOLE.125 4254.63,104 r0 top
MH4 "mounting hole" MTHOLE.125 4254.63,3529 r0 top
MH5 "mounting hole" MTHOLE.125 2579.63,3529 r0 top
MH6 "mounting hole" MTHOLE.125 3179.63,104 r0 top
RA1 "DNL, 0603" 0603R#1 2041.77,2208.37 r180 bottom
RA2 "0, 0603" 0603R#2 2041.77,2208.37 r180 top
RA3 "0, 0603" 0603R#2 2041.77,2258.37 r180 top
RA4 "DNL, 0603" 0603R#2 2041.77,2305.87 r180 top
RA5 "0, 0603" 0603R#2 1874.27,2258.37 r0 top
RA6 "DNL, 0603" 0603R#2 1874.27,2305.87 r0 top
RA7 "DNL, 0603" 0603R#2 2320.27,2245.87 r180 top
RA8 "DNL, 0603" 0603R#2 2211.77,2139.87 r90 top
RA9 "0, 0603" 0603R#2 2264.27,2195.87 r0 top
RA10 "10K, 1%, 0603" 0603R#2 3307.63,2250.43 r180 top
RA11 "806, 1%, 0603" 0603R#2 3012.63,2040.43 r90 top
RA12 "49.9, 1%, 0603" 0603R#2 3012.63,2139.43 r90 top
RA13 "49.9, 1%, 0603" 0603R#2 3719.63,2138 r90 top
RA14 "698, 1%, 0603" 0603R#2 3112.63,2085.43 r180 top
RA15 "100, 1%, 0603" 0603R#2 3112.63,2195.43 r180 top
RA16 "301, 1%, 0603" 0603R#2 3112.63,2140.43 r180 top
RA17 "49.9, 1%, 0603" 0603R#2 3402.63,2185.43 r0 top
RA18 "100, 1%, 0603" 0603R#2 3457.63,2140.43 r270 top
RA19 "49.9, 1%, 0603" 0603R#2 2737.63,2035.43 r90 top
RA20 "100, 1%, 0603" 0603R#2 2597.63,2085.43 r90 top
RA21 "49.9, 1%, 0603" 0603R#2 2787.63,1880.43 r0 top
RA22 "806, 1%, 0603" 0603R#2 2887.63,1880.43 r0 top
RA23 "49.9, 1%, 0603" 0603R#2 3012.63,1975.43 r270 top
RA24 "100, 1%, 0603" 0603R#2 3057.63,1920.43 r0 top
RA25 "301, 1%, 0603" 0603R#2 3057.63,1975.43 r0 top
RA26 "698, 1%, 0603" 0603R#2 3057.63,2030.43 r0 top
RA27 "49.9, 1%, 0603" 0603R#2 3402.63,1930.43 r0 top
RA28 "100, 1%, 0603" 0603R#2 3457.63,1975.43 r90 top
RA29 "49.9, 1%, 0603" 0603R#2 3717.63,1940.43 r90 top
RA30 "10K, 1%, 0603" 0603R#2 3299.63,1884 r180 top
RA31 "10K, 1%, 0603" 0603R#2 3344.63,1749 r180 top
RA32 "806, 1%, 0603" 0603R#2 3012.63,1540.43 r90 top
RA33 "49.9, 1%, 0603" 0603R#2 3012.63,1640.43 r90 top
RA34 "49.9, 1%, 0603" 0603R#2 3402.63,1685.43 r0 top
RA35 "100, 1%, 0603" 0603R#2 3457.63,1640.43 r270 top
RA36 "49.9, 1%, 0603" 0603R#2 3719.63,1638 r90 top
RA37 "100, 1%, 0603" 0603R#2 3112.63,1695.43 r180 top
RA38 "301, 1%, 0603" 0603R#2 3112.63,1640.43 r180 top
RA39 "698, 1%, 0603" 0603R#2 3112.63,1585.43 r180 top
RA40 "49.9, 1%, 0603" 0603R#2 2737.63,1540.43 r90 top
RA41 "100, 1%, 0603" 0603R#2 2537.63,1590.43 r90 top
RA42 "49.9, 1%, 0603" 0603R#2 2787.63,1385.43 r0 top
RA43 "DNL, 0603" 0603R#2 2106.77,1603.37 r90 top
RA44 "0, 0603" 0603R#2 2170.77,1583.37 r0 top
RA45 "301, 1%, 0603" 0603R#2 3057.63,1475.43 r0 top
RA46 "806, 1%, 0603" 0603R#2 2887.63,1385.43 r0 top
RA47 "49.9, 1%, 0603" 0603R#2 3012.63,1475.43 r270 top
RA48 "698, 1%, 0603" 0603R#2 3057.63,1530.43 r0 top
RA49 "DNL, 0603" 0603R#2 2226.77,1638.37 r180 top
RA50 "100, 1%, 0603" 0603R#2 3057.63,1420.43 r0 top
RA51 "49.9, 1%, 0603" 0603R#2 3402.63,1430.43 r0 top
RA52 "100, 1%, 0603" 0603R#2 3457.63,1475.43 r90 top
RA53 "49.9, 1%, 0603" 0603R#2 3720.63,1437.43 r90 top
RA54 "DNL, 0603" 0603R#2 1964.27,1659.37 r270 top
RA55 "10K, 1%, 0603" 0603R#2 3304.63,1384 r180 top
RA56 "0, 0603" 0603R#2 1784.27,1553.37 r0 top
RD1 "10K, 1%, 0603" 0603R#2 3342.63,724.43 r180 top
RD2 "49.9, 1%, 0603" 0603R#2 2947.63,669.43 r0 top
RD2SET1 "2K, 1%, 0603" 0603R#2 2044.63,429 r0 top
RD2SET2 "2K, 1%, 0603" 0603R#2 2055.63,879 r0 top
RD2SET3 "2K, 1%, 0603" 0603R#2 2054.63,2497 r0 top
RD2SET4 "2K, 1%, 0603" 0603R#2 2055.63,2960 r0 top
RD3 "49.9, 1%, 0603" 0603R#2 3402.63,664.43 r0 top
RD4 "200, 0603, 1%" 0603R#2 2947.63,614.43 r0 top
RD5 "100, 1%, 0603" 0603R#2 3102.63,669.43 r180 top
RD6 "301, 1%, 0603" 0603R#2 3102.63,614.43 r180 top
RD7 "698, 1%, 0603" 0603R#2 3102.63,559.43 r180 top
RD8 "806, 1%, 0603" 0603R#2 3457.63,609.43 r270 top
RD9 "0, 1%, 0603" 0603R#2 2612.63,604.43 r0 top
RD10 "49.9, 1%, 0603" 0603R#2 2337.63,514.43 r90 top
RD11 "0, 0603" 0603R#2 2392.63,624.43 r180 top
RD12 "200, 0603, 1%" 0603R#2 2947.63,559.43 r0 top
RD13 "25, 1%, 0603" 0603R#2 3722.63,604 r0 top
RD14 "100, 1%, 0603" 0603R#2 2567.63,624.43 r270 top
RD15 "DNL, 0603" 0603R#2 3002.63,504.43 r180 top
RD16 "49.9, 1%, 0603" 0603R#2 2392.63,569.43 r270 top
RD17 "200, 0603, 1%" 0603R#2 3002.63,449.43 r180 top
RD18 "25, 1%, 0603" 0603R#2 3722.63,538.37 r0 top
RD19 "0, 1%, 0603" 0603R#2 2612.63,509.43 r0 top
RD20 "DNL, 0603" 0603R#2 2157.13,429 r0 top
RD21 "301, 1%, 0603" 0603R#2 3047.63,449.43 r0 top
RD22 "49.9, 1%, 0603" 0603R#2 2947.63,394.43 r0 top
RD23 "100, 1%, 0603" 0603R#2 3047.63,394.43 r0 top
RD24 "698, 1%, 0603" 0603R#2 3046.63,504.43 r0 top
RD25 "806, 1%, 0603" 0603R#2 3455.63,446.43 r90 top
RD26 "200, 0603, 1%" 0603R#2 2732.63,359.43 r0 top
RD27 "49.9, 1%, 0603" 0603R#2 3397.63,394.43 r0 top
RD28 "0, 1%, 0603" 0603R#2 2157.13,359 r0 top
RD29 "10K, 1%, 0603" 0603R#2 3294.63,354 r180 top
RD30 "DNL, 0603" 0603R#2 2269.63,354 r0 top
RD31 "10K, 1%, 0603" 0603R#2 3342.63,1170.43 r180 top
RD32 "49.9, 1%, 0603" 0603R#2 2947.63,1115.43 r0 top
RD33 "49.9, 1%, 0603" 0603R#2 3402.63,1110.43 r0 top
RD34 "200, 0603, 1%" 0603R#2 2947.63,1060.43 r0 top
RD35 "100, 1%, 0603" 0603R#2 3102.63,1115.43 r180 top
RD36 "301, 1%, 0603" 0603R#2 3102.63,1060.43 r180 top
RD37 "698, 1%, 0603" 0603R#2 3102.63,1005.43 r180 top
RD38 "806, 1%, 0603" 0603R#2 3457.63,1055.43 r270 top
RD39 "0, 1%, 0603" 0603R#2 2612.63,1050.43 r0 top
RD40 "49.9, 1%, 0603" 0603R#2 2337.63,960.43 r90 top
RD41 "0, 0603" 0603R#2 2392.63,1070.43 r180 top
RD42 "200, 0603, 1%" 0603R#2 2947.63,1005.43 r0 top
RD43 "25, 1%, 0603" 0603R#2 3719.63,1040.37 r0 top
RD44 "100, 1%, 0603" 0603R#2 2567.63,1070.43 r270 top
RD45 "DNL, 0603" 0603R#2 3002.63,950.43 r180 top
RD46 "49.9, 1%, 0603" 0603R#2 2392.63,1015.43 r270 top
RD47 "200, 0603, 1%" 0603R#2 3002.63,895.43 r180 top
RD48 "25, 1%, 0603" 0603R#2 3719.63,986.37 r0 top
RD49 "0, 1%, 0603" 0603R#2 2612.63,955.43 r0 top
RD50 "DNL, 0603" 0603R#2 2158.63,879 r0 top
RD51 "301, 1%, 0603" 0603R#2 3047.63,895.43 r0 top
RD52 "49.9, 1%, 0603" 0603R#2 2947.63,840.43 r0 top
RD53 "100, 1%, 0603" 0603R#2 3047.63,840.43 r0 top
RD54 "698, 1%, 0603" 0603R#2 3046.63,950.43 r0 top
RD55 "806, 1%, 0603" 0603R#2 3455.63,892.43 r90 top
RD56 "200, 0603, 1%" 0603R#2 2732.63,805.43 r0 top
RD57 "49.9, 1%, 0603" 0603R#2 3397.63,840.43 r0 top
RD58 "0, 1%, 0603" 0603R#2 2157.63,824 r180 top
RD59 "10K, 1%, 0603" 0603R#2 3292.63,800.43 r180 top
RD60 "DNL, 0603" 0603R#2 2292.63,810.43 r0 top
RD61 "10K, 1%, 0603" 0603R#2 3347.63,2790.43 r180 top
RD62 "49.9, 1%, 0603" 0603R#2 2952.63,2735.43 r0 top
RD63 "49.9, 1%, 0603" 0603R#2 3407.63,2730.43 r0 top
RD64 "200, 0603, 1%" 0603R#2 2952.63,2680.43 r0 top
RD65 "100, 1%, 0603" 0603R#2 3107.63,2735.43 r180 top
RD66 "301, 1%, 0603" 0603R#2 3107.63,2680.43 r180 top
RD67 "698, 1%, 0603" 0603R#2 3107.63,2625.43 r180 top
RD68 "806, 1%, 0603" 0603R#2 3462.63,2675.43 r270 top
RD69 "0, 1%, 0603" 0603R#2 2617.63,2670.43 r0 top
RD70 "49.9, 1%, 0603" 0603R#2 2342.63,2580.43 r90 top
RD71 "0, 0603" 0603R#2 2397.63,2690.43 r180 top
RD72 "200, 0603, 1%" 0603R#2 2952.63,2625.43 r0 top
RD73 "25, 1%, 0603" 0603R#2 3725.63,2666 r0 top
RD74 "100, 1%, 0603" 0603R#2 2572.63,2690.43 r270 top
RD75 "DNL, 0603" 0603R#2 3007.63,2570.43 r180 top
RD76 "49.9, 1%, 0603" 0603R#2 2397.63,2635.43 r270 top
RD77 "200, 0603, 1%" 0603R#2 3007.63,2515.43 r180 top
RD78 "25, 1%, 0603" 0603R#2 3727.63,2475.43 r90 top
RD79 "0, 1%, 0603" 0603R#2 2617.63,2575.43 r0 top
RD80 "DNL, 0603" 0603R#2 2157.63,2497 r0 top
RD81 "301, 1%, 0603" 0603R#2 3052.63,2515.43 r0 top
RD82 "49.9, 1%, 0603" 0603R#2 2952.63,2460.43 r0 top
RD83 "100, 1%, 0603" 0603R#2 3052.63,2460.43 r0 top
RD84 "698, 1%, 0603" 0603R#2 3051.63,2570.43 r0 top
RD85 "806, 1%, 0603" 0603R#2 3460.63,2512.43 r90 top
RD86 "200, 0603, 1%" 0603R#2 2737.63,2425.43 r0 top
RD87 "49.9, 1%, 0603" 0603R#2 3402.63,2460.43 r0 top
RD88 "0, 1%, 0603" 0603R#2 2157.63,2438 r180 top
RD89 "10K, 1%, 0603" 0603R#2 3294.63,2419 r180 top
RD90 "DNL, 0603" 0603R#2 2297.63,2430.43 r0 top
RD91 "10K, 1%, 0603" 0603R#2 3352.63,3245.43 r180 top
RD92 "49.9, 1%, 0603" 0603R#2 2957.63,3190.43 r0 top
RD93 "49.9, 1%, 0603" 0603R#2 3412.63,3185.43 r0 top
RD94 "200, 0603, 1%" 0603R#2 2957.63,3135.43 r0 top
RD95 "100, 1%, 0603" 0603R#2 3112.63,3190.43 r180 top
RD96 "301, 1%, 0603" 0603R#2 3112.63,3135.43 r180 top
RD97 "698, 1%, 0603" 0603R#2 3112.63,3080.43 r180 top
RD98 "806, 1%, 0603" 0603R#2 3467.63,3130.43 r270 top
RD99 "0, 1%, 0603" 0603R#2 2622.63,3125.43 r0 top
RD100 "49.9, 1%, 0603" 0603R#2 2347.63,3035.43 r90 top
RD101 "0, 0603" 0603R#2 2402.63,3145.43 r180 top
RD102 "200, 0603, 1%" 0603R#2 2957.63,3080.43 r0 top
RD103 "25, 1%, 0603" 0603R#2 3733.63,3110 r0 top
RD104 "100, 1%, 0603" 0603R#2 2577.63,3145.43 r270 top
RD105 "DNL, 0603" 0603R#2 3012.63,3025.43 r180 top
RD106 "49.9, 1%, 0603" 0603R#2 2402.63,3090.43 r270 top
RD107 "200, 0603, 1%" 0603R#2 3012.63,2970.43 r180 top
RD108 "25, 1%, 0603" 0603R#2 3732.63,2930.43 r90 top
RD109 "0, 1%, 0603" 0603R#2 2622.63,3030.43 r0 top
RD110 "DNL, 0603" 0603R#2 2161.63,2960 r0 top
RD111 "301, 1%, 0603" 0603R#2 3057.63,2970.43 r0 top
RD112 "49.9, 1%, 0603" 0603R#2 2957.63,2915.43 r0 top
RD113 "100, 1%, 0603" 0603R#2 3057.63,2915.43 r0 top
RD114 "698, 1%, 0603" 0603R#2 3056.63,3025.43 r0 top
RD115 "806, 1%, 0603" 0603R#2 3465.63,2967.43 r90 top
RD116 "200, 0603, 1%" 0603R#2 2742.63,2880.43 r0 top
RD117 "49.9, 1%, 0603" 0603R#2 3407.63,2915.43 r0 top
RD118 "0, 1%, 0603" 0603R#2 2161.63,2905 r180 top
RD119 "10K, 1%, 0603" 0603R#2 3302.63,2875.43 r180 top
RD120 "DNL, 0603" 0603R#2 2302.63,2885.43 r0 top
RG1 "0, 0805" SM/R_0805 4278,962 r180 bottom
RP1 "200, 1%, 0603" 0603R#2 1074.63,629 r90 top
RP2 "200, 1%, 0603" 0603R#2 1089.63,859 r90 top
RP3 "200, 1%, 0603" 0603R#2 1094.63,1214 r90 top
RP4 "10K, 1%, 0603" 0603R#2 449.63,480 r270 top
RP5 "169K, 1%, 0603" 0603R#1 1554.63,1544 r270 bottom
RP6 "100K, 1%, 0603" 0603R#1 1554.63,1449 r270 bottom
RP7 "DNL, 0805" 0805R#1 1364.63,1509 r0 bottom
RP8 "301, 1%, 0603" 0603R#1 1356.63,2381 r90 bottom
RP9 "169K, 1%, 0603" 0603R#2 2452.63,1539 r270 top
RP10 "100K, 1%, 0603" 0603R#2 2397.63,1429 r0 top
RP11 "DNL, 0805" 0805R#2 2192.63,1369 r0 top
RP12 "301, 1%, 0603" 0603R#1 2402.63,1947 r270 bottom
RP13 "DNL, 0805" 0805R#2 564.63,3229 r270 top
RP14 "309K, 1%, 0603" 0603R#1 2324.63,3387 r270 bottom
RP15 "100K, 1%, 0603" 0603R#1 2379.63,3331 r90 bottom
RP16 "DNL, 0805" 0805R#1 2002.63,3449 r0 bottom
RP17 "499, 1%, 0805" 0805R#1 2294.63,3529 r0 bottom
RP19 "499, 1%, 0805" 0805R#1 2909.63,149 r0 bottom
RP20 "309K, 1%, 0603" 0603R#1 2514.63,318 r90 bottom
RP21 "10K, 1%, 0603" 0603R#2 2032.63,1374 r180 top
RP22 "100K, 1%, 0603" 0603R#2 2032.63,1433.37 r180 top
RP23 "10K, 1%, 0603" 0603R#2 1977.63,1493.37 r0 top
RP24 "100K, 1%, 0603" 0603R#1 2569.63,375 r270 bottom
RP25 "10K, 1%, 0603" 0603R#2 3697.63,1893.37 r180 top
RP26 "10K, 1%, 0603" 0603R#2 2095.63,1255.37 r90 top
RP27 "20K, 1%, 0603" 0603R#2 3775.63,1940.37 r90 top
RP28 "10K, 1%, 0603" 0603R#2 2037.63,1253.37 r90 top
RP29 "5K, 1%, 0603" 0603R#2 3793.63,1893.37 r180 top
RP30 "20K, 1%, 0603" 0603R#2 2150.63,1254.37 r90 top
RP31 "20K, 1%, 0603" 0603R#2 1977.63,1253.37 r90 top
RP32 "10K, 1%, 0603" 0603R#2 3697.63,1393.37 r180 top
RP33 "20K, 1%, 0603" 0603R#2 3782.63,1493.37 r270 top
RP34 "5K, 1%, 0603" 0603R#2 3797.63,1393.37 r180 top
RP35 "301, 1%, 0603" 0603R#1 1264.63,264 r270 bottom
RP36 "DNL, 0805" 0805R#1 1724.63,2909 r0 bottom
RP37 "DNL, 0805" 0805R#1 1710.63,2449 r0 bottom
RP38 "DNL, 0805" 0805R#1 1859.27,1913.37 r0 bottom
RP39 "DNL, 0805" 0805R#1 1730.63,834 r0 bottom
RP40 "DNL, 0805" 0805R#1 1731.63,388 r0 bottom
RP54 "10K, 1%, 0603" 0603R#2 3935,2314 r270 top
RP55 "5K, 1%, 0603" 0603R#2 3805,2259 r90 top
RP56 "20K, 1%, 0603" 0603R#2 3870,2314 r270 top
RP57 "10K, 1%, 0603" 0603R#2 3925,1814 r270 top
RP58 "5K, 1%, 0603" 0603R#2 3805,1759 r90 top
RP59 "20K, 1%, 0603" 0603R#2 3865,1814 r270 top
UA1 "LTC2299 ADC x2" QFN64(9X9) 1949.14,1913.64 r180 top
UA2 "AD8139_DiffAmp" SO8/L200#1 2942.63,2150.43 r180 top
UA3 "SN74CBT3253CPWR" TSSOP16 3182.63,1945.43 r0 top
UA4 "AD8139_DiffAmp" SO8/L200#1 3667.63,2165.43 r180 top
UA5 "AD8139_DiffAmp" SO8/L200#1 2942.63,1655.43 r180 top
UA6 "SN74CBT3253CPWR" TSSOP16 3182.63,1445.43 r0 top
UA7 "AD8139_DiffAmp" SO8/L200#1 3667.63,1665.43 r180 top
UD1 "LTC1668IG  DAC" SOG.65M/28/WG8.20/L10.16 1689.03,705.83 r270 top
UD2 "SN74CBT3253CPWR" SOG.65M/16/PW 3172.63,414.43 r0 top
UD3 "AD8139_DiffAmp" SO8/L200#1 3517.63,439.43 r0 top
UD4 "AD8022AR" SO8/L200#1 2877.63,629.43 r180 top
UD5 "LTC1668IG  DAC" SOG.65M/28/WG8.20/L10.16 1689.03,1151.83 r270 top
UD6 "SN74CBT3253CPWR" SOG.65M/16/PW 3172.63,860.43 r0 top
UD7 "AD8139_DiffAmp" SO8/L200#1 3517.63,885.43 r0 top
UD8 "AD8022AR" SO8/L200#1 2874.63,1074 r180 top
UD9 "LTC1668IG  DAC" SOG.65M/28/WG8.20/L10.16 1694.03,2771.83 r270 top
UD10 "SN74CBT3253CPWR" SOG.65M/16/PW 3177.63,2480.43 r0 top
UD11 "AD8139_DiffAmp" SO8/L200#1 3522.63,2505.43 r0 top
UD12 "AD8022AR" SO8/L200#1 2879.63,2694 r180 top
UD13 "LTC1668IG  DAC" SOG.65M/28/WG8.20/L10.16 1699.03,3226.83 r270 top
UD14 "SN74CBT3253CPWR" SOG.65M/16/PW 3182.63,2935.43 r0 top
UD15 "AD8139_DiffAmp" SO8/L200#1 3527.63,2960.43 r0 top
UD16 "AD8022AR" SO8/L200#1 2884.63,3149 r180 top
UP1 "LT1962EMS8" MSOP-8#1 1489.63,1449 r270 bottom
UP2 "LT1962EMS8" MSOP-8#2 2332.63,1424 r90 top
UP3 "LT1962EMS8" MSOP-8#1 2192.63,3389 r270 bottom
UP5 "ADC128S102 ADC 8Ch" TSSOP16 1755.93,1245.8 r0 top
UP6 "ADT7301 TempSensor" SOT23-6 1712.63,1318.37 r90 top
UP7 "LT1962EMS8" SO8/L200#2 2454.63,104 r90 bottom
UT31 "SN74AVCB164245 Transceiver" TSSOP48_.4MMPITCH_NARROW 1188.63,2603.37 r90 bottom
UT32 "SN74AVCB164245 Transceiver" TSSOP48_.4MMPITCH_NARROW 1189.63,553.37 r90 bottom
UT35 "SN74AVCB164245 Transceiver" TSSOP48_.4MMPITCH_NARROW 1188.63,1784.37 r90 bottom
UT40 "SN74AVCB164245 Transceiver" TSSOP48_.4MMPITCH_NARROW 1187.63,962.37 r90 bottom
UT45 "SN74AVCB164245 Transceiver" TSSOP48_.4MMPITCH_NARROW 1189.63,3015.37 r90 bottom
UT50 "SN74AVCB164245 Transceiver" TSSOP48_.4MMPITCH_NARROW 1188.63,2193.37 r90 bottom
UT55 "SN74AVCB164245 Transceiver" TSSOP48_.4MMPITCH_NARROW 1189.63,1374.37 r90 bottom
UT60 "SN74AVCB164245 Transceiver" TSSOP48_.4MMPITCH_NARROW 1188.63,3428.37 r90 bottom
UT61 "22ohm Resistor array Y1220CT-ND Panasonic" RN8.150X63 820.13,950.37 r90 bottom
UT62 "22ohm Resistor array Y1220CT-ND Panasonic" RN8.150X63 820.13,755.37 r90 bottom
UT63 "22ohm Resistor array Y1220CT-ND Panasonic" RN8.150X63 815.13,1360.37 r90 bottom
UT64 "22ohm Resistor array Y1220CT-ND Panasonic" RN8.150X63 815.13,1165.37 r90 bottom
UT65 "22ohm Resistor array Y1220CT-ND Panasonic" RN8.150X63 815.13,3002.37 r90 bottom
UT66 "22ohm Resistor array Y1220CT-ND Panasonic" RN8.150X63 815.13,2810.37 r90 bottom
UT67 "22ohm Resistor array Y1220CT-ND Panasonic" RN8.150X63 815.13,3415.37 r90 bottom
UT68 "22ohm Resistor array Y1220CT-ND Panasonic" RN8.150X63 815.13,3220.37 r90 bottom
UT69 "22ohm Resistor array Y1220CT-ND Panasonic" RN8.150X63 815.13,2180.37 r90 bottom
UT70 "22ohm Resistor array Y1220CT-ND Panasonic" RN8.150X63 815.13,1985.37 r90 bottom
UT71 "22ohm Resistor array Y1220CT-ND Panasonic" RN8.150X63 815.13,1770.37 r90 bottom
UT72 "22ohm Resistor array Y1220CT-ND Panasonic" RN8.150X63 815.13,1575.37 r90 bottom
UT73 "22ohm Resistor array Y1220CT-ND Panasonic" RN8.150X63 819.13,540.37 r90 bottom
UT74 "22ohm Resistor array Y1220CT-ND Panasonic" RN8.150X63 815.13,2398.37 r90 bottom
UT75 "22ohm Resistor array Y1220CT-ND Panasonic" RN8.150X63 815.13,2590.37 r90 bottom

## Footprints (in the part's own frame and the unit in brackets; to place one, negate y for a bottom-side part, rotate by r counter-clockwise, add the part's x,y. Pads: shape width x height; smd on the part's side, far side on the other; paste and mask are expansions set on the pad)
0603C#1 [mil]
  rect 32x32 smd: 1(0,0) 2(56,0)
  silkscreen extent 19,-15 37,14
0603C#2 [mil]
  round 0 smd: 1(0,0) 2(56,0)
  silkscreen extent 19,-15 37,14
0603C_REV1 [mil]
  rect 32x32 smd: 1(0,0) 2(56,0)
  silkscreen extent 19,-15 37,14
0603R#1 [mil]
  round 0 smd: 1(0,0) 2(56,0)
  silkscreen extent 19,-15 37,14
0603R#2 [mil]
  rect 32x32 smd: 1(0,0) 2(56,0)
  silkscreen extent 19,-15 37,14
0805C [mil]
  rect 50x50 smd: 1(0,0) 2(84,0)
  silkscreen extent 31,-20 52,20
0805L#1 [mil]
  round 0 smd: 1(0,0) 2(84,0)
  silkscreen extent 31,-20 52,20
0805L#2 [mil]
  rect 50x50 smd: 1(0,0) 2(84,0)
  silkscreen extent 31,-20 52,20
0805R#1 [mil]
  round 0 smd: 1(0,0) 2(84,0)
  silkscreen extent 31,-20 52,20
0805R#2 [mil]
  rect 50x50 smd: 1(0,0) 2(84,0)
  silkscreen extent 31,-20 52,20
BLKCON.100/VH/TM1SQS/W.100/2 [mil]
  round 62 hole 42: 1(0,0) 2(100,0)
  silkscreen extent -55,-50 155,50
CHOKEPM54 [mil]
  rect 118.1x216.53 smd: 1(0,0) 2(196.67,0)
  silkscreen extent 20,-114 205,114
CON_AMP_1MM_64PINS [mil]
  rect 23.6x106.3 smd: 1(0,0) 2(0,-129.92) 3(-39.37,0) 4(-39.37,-129.92) 5(-78.73,0) 6(-78.73,-129.92) 7(-118.1,0) 8(-118.1,-129.92) 9(-157.47,0) 10(-157.47,-129.92) 11(-196.83,0) 12(-196.83,-129.92) 13(-236.2,0) 14(-236.2,-129.92) 15(-275.57,0) 16(-275.57,-129.92) 17(-314.93,0) 18(-314.93,-129.92) 19(-354.3,0) 20(-354.3,-129.92) 21(-393.67,0) 22(-393.67,-129.92) 23(-433.03,0) 24(-433.03,-129.92) 25(-472.4,0) 26(-472.4,-129.92) 27(-511.77,0) 28(-511.77,-129.92) 29(-551.13,0) 30(-551.13,-129.92) 31(-590.5,0) 32(-590.5,-129.92) 33(-629.87,0) 34(-629.87,-129.92) 35(-669.23,0) 36(-669.23,-129.92) 37(-708.6,0) 38(-708.6,-129.92) 39(-747.97,0) 40(-747.97,-129.92) 41(-787.33,0) 42(-787.33,-129.92) 43(-826.7,0) 44(-826.7,-129.92) 45(-866.07,0) 46(-866.07,-129.92) 47(-905.43,0) 48(-905.43,-129.92) 49(-944.8,0) 50(-944.8,-129.92) 51(-984.17,0) 52(-984.17,-129.92) 53(-1023.53,0) 54(-1023.53,-129.92) 55(-1062.9,0) 56(-1062.9,-129.92) 57(-1102.27,0) 58(-1102.27,-129.92) 59(-1141.63,0) 60(-1141.63,-129.92) 61(-1181,0) 62(-1181,-129.92) 63(-1220.37,0) 64(-1220.37,-129.92)
  round 56 hole 55 unplated: HOLE1(-1287.4,-64.9) HOLE2(66.92,-64.95)
  silkscreen extent -1320,-199 98,71
CON_AMP_1MM_84PINS [mil]
  rect 23.6x106.3 smd: 1(0,0) 2(0,-129.92) 3(-39.37,0) 4(-39.37,-129.92) 5(-78.73,0) 6(-78.73,-129.92) 7(-118.1,0) 8(-118.1,-129.92) 9(-157.47,0) 10(-157.47,-129.92) 11(-196.83,0) 12(-196.83,-129.92) 13(-236.2,0) 14(-236.2,-129.92) 15(-275.57,0) 16(-275.57,-129.92) 17(-314.93,0) 18(-314.93,-129.92) 19(-354.3,0) 20(-354.3,-129.92) 21(-393.67,0) 22(-393.67,-129.92) 23(-433.03,0) 24(-433.03,-129.92) 25(-472.4,0) 26(-472.4,-129.92) 27(-511.77,0) 28(-511.77,-129.92) 29(-551.13,0) 30(-551.13,-129.92) 31(-590.5,0) 32(-590.5,-129.92) 33(-629.87,0) 34(-629.87,-129.92) 35(-669.23,0) 36(-669.23,-129.92) 37(-708.6,0) 38(-708.6,-129.92) 39(-747.97,0) 40(-747.97,-129.92) 41(-787.33,0) 42(-787.33,-129.92) 43(-826.7,0) 44(-826.7,-129.92) 45(-866.07,0) 46(-866.07,-129.92) 47(-905.43,0) 48(-905.43,-129.92) 49(-944.8,0) 50(-944.8,-129.92) 51(-984.17,0) 52(-984.17,-129.92) 53(-1023.53,0) 54(-1023.53,-129.92) 55(-1062.9,0) 56(-1062.9,-129.92) 57(-1102.27,0) 58(-1102.27,-129.92) 59(-1141.63,0) 60(-1141.63,-129.92) 61(-1181,0) 62(-1181,-129.92) 63(-1220.37,0) 64(-1220.37,-129.92) 65(-1259.73,0) 66(-1259.73,-129.92) 67(-1299.1,0) 68(-1299.1,-129.92) 69(-1338.47,0) 70(-1338.47,-129.92) 71(-1377.83,0) 72(-1377.83,-129.92) 73(-1417.2,0) 74(-1417.2,-129.92) 75(-1456.57,0) 76(-1456.57,-129.92) 77(-1495.93,0) 78(-1495.93,-129.92) 79(-1535.3,0) 80(-1535.3,-129.92) 81(-1574.67,0) 82(-1574.67,-129.92) 83(-1614.03,0) 84(-1614.03,-129.92)
  round 56 hole 55 unplated: HOLE1(-1681.1,-64.95) HOLE2(66.92,-64.95)
  silkscreen extent -1711,-199 98,71
DSUB/RS.318/TM/15 [mil]
  rect 63x63 hole 42: 1(0,0) 10(163.5,112)
  round 63 hole 42: 2(109,0) 3(218,0) 4(327,0) 5(436,0) 6(545,0) 7(654,0) 8(763,0) 9(54.5,112) 11(272.5,112) 12(381.5,112) 13(490.5,112) 14(599.5,112) 15(708.5,112)
  round 120 hole 120: Hole29(1037.5,56) Hole30(-274.5,56)
  silkscreen extent -406,-76 1169,662
HEADER_AMP146128 [mil]
  rect 50x140 smd: 1(0,0) 2(100,-105)
  silkscreen extent -25,-100 125,-10
MSOP-8#1 [mil]
  round 0 smd: 1(0,0) 2(25.6,0) 3(51.2,0) 4(76.8,0) 5(76.75,192.9) 6(51.17,192.9) 7(25.58,192.9) 8(0,192.9)
  silkscreen extent -20,43 98,151
MSOP-8#2 [mil]
  rect 16x68.87 smd: 1(0,0)
  oval 16x68.87 smd: 2(25.6,0) 3(51.2,0) 4(76.8,0) 5(76.75,192.9) 6(51.17,192.9) 7(25.58,192.9) 8(0,192.9)
  silkscreen extent -20,43 98,151
MTHOLE.125 [mil]
  round 125 hole 125 unplated: 1(0,0)
QFN64(9X9) [mm]
  rect 0.66x0.254 smd: 1(-4.425,3.75) 2(-4.425,3.25) 3(-4.425,2.75) 4(-4.425,2.25) 5(-4.425,1.75) 6(-4.425,1.25) 7(-4.425,0.75) 8(-4.425,0.25) 9(-4.425,-0.25) 10(-4.425,-0.75) 11(-4.425,-1.25) 12(-4.425,-1.75) 13(-4.425,-2.25) 14(-4.425,-2.75) 15(-4.425,-3.25) 16(-4.425,-3.75) 33(4.425,-3.75) 34(4.425,-3.25) 35(4.425,-2.75) 36(4.425,-2.25) 37(4.425,-1.75) 38(4.425,-1.25) 39(4.425,-0.75) 40(4.425,-0.25) 41(4.425,0.25) 42(4.425,0.75) 43(4.425,1.25) 44(4.425,1.75) 45(4.425,2.25) 46(4.425,2.75) 47(4.425,3.25) 48(4.425,3.75)
  rect 0.254x0.66 smd: 17(-3.75,-4.425) 18(-3.25,-4.425) 19(-2.75,-4.425) 20(-2.25,-4.425) 21(-1.75,-4.425) 22(-1.25,-4.425) 23(-0.75,-4.425) 24(-0.25,-4.425) 25(0.25,-4.425) 26(0.75,-4.425) 27(1.25,-4.425) 28(1.75,-4.425) 29(2.25,-4.425) 30(2.75,-4.425) 31(3.25,-4.425) 32(3.75,-4.425) 49(3.75,4.425) 50(3.25,4.425) 51(2.75,4.425) 52(2.25,4.425) 53(1.75,4.425) 54(1.25,4.425) 55(0.75,4.425) 56(0.25,4.425) 57(-0.25,4.425) 58(-0.75,4.425) 59(-1.25,4.425) 60(-1.75,4.425) 61(-2.25,4.425) 62(-2.75,4.425) 63(-3.25,4.425) 64(-3.75,4.425)
  rect 7.15x7.15 smd: 65(0,0)
  silkscreen extent -4.5,-4.5 4.5,4.5
RN8.150X63 [mil]
  round 0 smd: 1(0,0) 2(-23,0) 3(-43,0) 4(-62,0) 5(-82,0) 6(-102,0) 7(-121,0) 8(-144,0) 9(-144,-71) 10(-121,-71) 11(-102,-71) 12(-82,-71) 13(-62,-71) 14(-43,-71) 15(-23,-71) 16(0,-71)
  silkscreen extent -156,-46 11,-24
"SHIELD 2.75X3.00" [mil]
  rect 210x75 smd: 1(380.6,37.25) 2(880.6,37.25) 3(1380.6,37.25) 4(1880.6,37.25) 5(2380.6,37.25) 6(2880.6,37.25) 12(2880.6,-2799.75) 13(2380.6,-2799.75) 14(1880.6,-2799.75) 15(1380.6,-2799.75) 16(880.6,-2799.75) 17(380.6,-2799.75)
  rect 75x210 smd: 7(3049.1,-381.25) 8(3049.1,-881.25) 9(3049.1,-1381.25) 10(3049.1,-1881.25) 11(3049.1,-2381.25) 18(-37.9,-2631.25) 19(-37.9,-2131.25) 20(-37.9,-1631.25) 21(-37.9,-1131.25) 22(-37.9,-631.25) 23(-37.9,-131.25)
SM/R_0805 [mil]
  round 0 smd: 1(0,0) 2(-84,0)
  silkscreen extent -122,-38 38,38
SO8/L200#1 [mil]
  rect 25x94 smd: 1(0,0)
  oval 25x94 smd: 2(50,0) 3(100,0) 4(150,0) 5(150,196) 6(100,196) 7(50,196) 8(0,196)
  silkscreen extent -23,60 174,136
SO8/L200#2 [mil]
  round 0 smd: 1(0,0) 2(50,0) 3(100,0) 4(150,0) 5(150,196) 6(100,196) 7(50,196) 8(0,196)
  silkscreen extent -23,60 174,136
SOG.65M/16/PW [mil]
  rect 16x70 smd: 1(0,0)
  oval 16x70 smd: 2(25.6,0) 3(51.2,0) 4(76.8,0) 5(102.4,0) 6(128,0) 7(153.6,0) 8(179.08,0) 9(179.08,238.58) 10(153.5,238.58) 11(127.92,238.58) 12(102.33,238.58) 13(76.75,238.58) 14(51.17,238.58) 15(25.58,238.58) 16(0,238.58)
  silkscreen extent -16,35 193,205
SOG.65M/28/WG8.20/L10.16 [mil]
  rect 16x90 smd: 1(0,0) 10(230.4,0) 20(204.8,270)
  oval 16x90 smd: 2(25.6,0) 3(51.2,0) 4(76.8,0) 5(102.4,0) 6(128,0) 7(153.6,0) 8(179.2,0) 9(204.8,0) 11(256,0) 12(281.6,0) 13(307.2,0) 14(332.8,0) 15(332.8,270) 16(307.2,270) 17(281.6,270) 18(256,270) 19(230.4,270) 21(179.2,270) 22(153.6,270) 23(128,270) 24(102.4,270) 25(76.8,270) 26(51.2,270) 27(25.6,270) 28(0,270)
  silkscreen extent -34,60 366,210
SOT23-6 [mil]
  rect 27x39 smd: 1(0,0) 2(37.5,0) 3(75,0) 4(75,102) 5(37.4,102) 6(0,101.97)
  silkscreen extent -22,26 97,79
TANT4532 [mil]
  rect 80x120 smd: 1(0,0) 2(180,0)
  silkscreen extent -83,-67 228,102
TANTA#1 [mil]
  rect 60x60 smd: 1(0,0) 2(130,0)
  silkscreen extent -12,-60 95,25
TANTA#2 [mil]
  round 0 smd: 1(0,0) 2(130,0)
  silkscreen extent -12,-60 95,25
TSSOP16 [mil]
  rect 16x70.47 smd: 1(0,0)
  oval 16x70.47 smd: 2(25.6,0) 3(51.2,0) 4(76.8,0) 5(102.4,0) 6(128,0) 7(153.6,0) 8(179.13,0) 9(179.13,234.25) 10(153.55,234.25) 11(127.95,234.25) 12(102.37,234.25) 13(76.77,234.25) 14(51.18,234.25) 15(25.58,234.25) 16(0,234.25)
  silkscreen extent -12,43 185,193
TSSOP48_.4MMPITCH_NARROW [mil]
  round 0 smd: 1(0,0) 2(-15.7,0) 3(-31.4,0) 4(-47.1,0) 5(-62.8,0) 6(-78.5,0) 7(-94.2,0) 8(-109.9,0) 9(-125.6,0) 10(-141.3,0) 11(-157,0) 12(-172.7,0) 13(-188.4,0) 14(-204.1,0) 15(-219.8,0) 16(-235.5,0) 17(-251.2,0) 18(-266.9,0) 19(-282.6,0) 20(-298.3,0) 21(-314,0) 22(-329.7,0) 23(-345.4,0) 24(-361.1,0) 25(-361.1,-212.6) 26(-345.4,-212.6) 27(-329.7,-212.6) 28(-314,-212.6) 29(-298.3,-212.6) 30(-282.6,-212.6) 31(-266.9,-212.6) 32(-251.2,-212.6) 33(-235.5,-212.6) 34(-219.8,-212.6) 35(-204.1,-212.6) 36(-188.4,-212.6) 37(-172.7,-212.6) 38(-157,-212.6) 39(-141.3,-212.6) 40(-125.6,-212.6) 41(-109.9,-212.6) 42(-94.2,-212.6) 43(-78.5,-212.6) 44(-62.8,-212.6) 45(-47.1,-212.6) 46(-31.4,-212.6) 47(-15.7,-212.6) 48(0,-212.6)
  silkscreen extent -374,-161 12,-55

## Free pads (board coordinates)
  round 25 hole 12: 1(114.33,3353.43) 1(404.85,3353.43) 1(1275.63,1850) 1(1292.63,2208) 1(1304.63,208) 1(1356.63,2492) 1(1943.27,1855.87) 1(1943.27,1970.87) 1(1988.51,1788.64) 1(2067.25,1825.06) 1(2067.25,2002.22) 1(2666.63,865.43) 1(2907.63,867) 1(2907.63,970.43) 1(2939.63,792) 1(3517,2302)

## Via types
v1: diameter 25, hole 12, Top Layer to Bottom Layer, 692 vias
v2: diameter 40, hole 20, Top Layer to Bottom Layer, 39 vias
v3: diameter 35, hole 20, Top Layer to Bottom Layer, 23 vias
v4: diameter 22, hole 12, Top Layer to Bottom Layer, 3 vias

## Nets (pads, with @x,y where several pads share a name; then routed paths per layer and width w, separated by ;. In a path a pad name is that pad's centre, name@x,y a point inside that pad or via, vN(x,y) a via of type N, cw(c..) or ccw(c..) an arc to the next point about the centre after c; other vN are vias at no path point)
A15: 
A15_11102: 
B15: 
B15_11282: 
CLOCK_IN1: J3.43 UT75.12 | length 739.8
  Top Layer w7: v1(114.33,2526.73) J3.43@194.63,2526.73
  Bottom Layer w7: v1(114.33,2526.73) 403,2526.73 419.63,2542.37 429.63,2553.37 482.63,2553.37 527.63,2508.37 UT75.12@744.13,2508.37
CLOCK_IN2: J3.44 UT75.11 | length 437.5
  Top Layer w7: J3.44@324.55,2526.73 452.87,2526.73 v1(453.63,2527.5)
  Bottom Layer w7: v1(453.63,2527.5) 453.63,2528 454.63,2528 454.63,2528.5 484.5,2528.5 524.63,2488.37 UT75.11@744.13,2488.37
COMB1_DATA0: J5.49 UT61.16 | length 745.8
  Top Layer w7: v1(114.33,963.57) J5.49@194.63,963.57
  Bottom Layer w7: v1(114.33,963.57) 129.63,978.87 434.5,978.87 449.63,994 619.63,994 663.27,950.37 UT61.16@749.13,950.37
COMB1_DATA1: J5.50 UT61.15 | length 439.8
  Top Layer w7: J5.50@324.55,963.57 453.33,963.57 453.63,963.87 v1(454.63,963.87)
  Bottom Layer w7: v1(454.63,963.87) 624.77,963.87 661.27,927.37 UT61.15@749.13,927.37
COMB1_DATA2: J5.51 UT61.14 | length 839.9
  Top Layer w7: v1(65.55,923.43) 66.32,924.2 J5.51@194.63,924.2
  Bottom Layer w7: v1(65.55,923.43) 231.2,923.43 255.63,947.87 416.63,947.87 425.63,938.87 619.5,938.87 651,907.37 UT61.14@749.13,907.37
COMB1_DATA3: J5.52 UT61.13 | length 439.4
  Top Layer w7: J5.52@324.55,924.2 v1(404.85,924.2)
  Bottom Layer w7: v1(404.85,924.2) 604.43,924.2 640.27,888.37 UT61.13@749.13,888.37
